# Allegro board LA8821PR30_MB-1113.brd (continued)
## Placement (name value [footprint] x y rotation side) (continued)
PR961  -  [R_0402NEW]  128.65 28.66 180 top
PR962  -  [R_0402NEW]  127.73 31.72 90 top
PR963  -  [R_0402NEW]  128.62 32.64 270 top
PR964  -  [R_0402NEW]  188.28 68.25 180 top
PR965  -  [R_0402NEW]  191.18 70.7 180 top
PR966  -  [R_0402NEW]  191.18 69.81 180 top
PR967  -  [R_0402NEW]  193.4 68.53 270 top
PR968  -  [R_0402NEW]  187.37 67.34 0 top
PR969  -  [R_0402NEW]  183.06 70.47 0 top
PR970  -  [R_0402NEW]  186.25 77.85 0 top
PR971  -  [R_0402NEW]  186 69.34 90 top
PT1  -  [TPC12]  140.67 37.63 0 top
PT2  -  [TPC12]  140.37 34.12 0 top
PT3  -  [TPC12]  193.22 59.54 0 top
PT4  -  [TPC12]  200.77 63.92 0 top
PT5  -  [TPC12]  186.7 58.46 0 top
PT6  -  [TPC12]  196.31 54.1 0 top
PT7  -  [TPC12]  110.83 49.4 180 top
PT8  -  [TPC12]  117.18 49.87 270 top
PT9  -  [TPC12]  48.33 23.9 270 top
PT10  -  [TPC12]  32.8 18.96 180 top
PT11  -  [TPC12]  17.2 65.75 180 top
PT12  -  [TPC12]  17.22 69.34 90 top
PT13  -  [TPC12]  24.7 69.25 180 top
PT14  -  [TPC12]  20.89 72.86 270 top
PT15  -  [TPC12]  29.42 63.06 0 top
PT16  -  [TPC12]  33.92 63.89 180 top
PT17  -  [TPC12]  25.31 65.52 90 top
PT18  -  [TPC12]  27.26 63.59 0 top
PT19  -  [TPC12]  189.77 79.41 0 top
PT20  -  [TPC12]  153.17 41 0 top
PU2  -  [ISL9519HRTZ-T_TQFN28_4X4]  147.12 39.46 0 bottom
PU300  -  [RT8207MZQW_WQFN20_3X3]  32.17 23.47 180 top
PU400  -  [SY8033BDBC_DFN10_3X3]  103.33 49.27 90 bottom
PU401  -  [SY8033BDBC_DFN10_3X3]  168.51 38.71 90 bottom
PU500  -  [TPS51212DSCR_SON10_3X3]  126.15 47.92 180 top
PU501  -  [RT8243BZQW_WQFN20_3X3]  194.34 57.52 180 top
PU600  -  [TPS51461RGER_QFN24_4X4]  111.36 81.21 180 bottom
PU700  -  [ISL95835HRTZ-T_TQFN40_5X5]  21.77 83.05 0 bottom
PU702  -  [INA199A2DCKR_SC70-6]  125.34 29.04 0 top
Q4  -  [SSM3K7002FU_SC70-3]  107.18 38.7 270 top
Q5  -  [SSM3K7002FU_SC70-3]  132.71 51.52 90 top
Q32  -  [SSM3K7002FU_SC70-3]  130.04 54.06 270 top
Q34  -  [SSM3K7002FU_SC70-3]  169.22 46.76 180 top
Q35  -  [DMN66D0LDW-7_SOT363-6]  150.96 67.73 180 top
Q37  -  [SSM3K7002FU_SC70-3]  59.96 46.71 90 bottom
Q38  -  [SSM3K7002FU_SC70-3]  59.96 49.13 90 bottom
Q41  -  [AO3419L_SOT23-3]  130.36 58.79 180 top
Q42  -  [SSM3K7002FU_SC70-3]  179.25 74.32 180 top
Q47  -  [SI2301CDS-T1-GE3_SOT23-3]  182.43 74.66 180 top
Q70  -  [SI3457BDV-T1-E3_TSOP6]  164.08 80.88 90 top
Q71  -  [SSM3K7002FU_SC70-3]  161.54 85.05 90 top
Q305  -  [DMN66D0LDW-7_SOT363-6]  166.11 84.69 270 top
Q311  -  [SSM3K7002FU_SC70-3]  175.32 28.35 0 top
Q316  -  [DMN66D0LDW-7_SOT363-6]  221.82 24.27 270 top
Q317  -  [DMN66D0LDW-7_SOT363-6]  227.96 8.96 90 top
Q318  -  [DMN66D0LDW-7_SOT363-6]  226.06 7.85 270 top
Q319  -  [DMN66D0LDW-7_SOT363-6]  226.06 12.68 270 top
Q320  -  [DMN66D0LDW-7_SOT363-6]  226.06 5.44 270 top
Q321  -  [SSM3K7002FU_SC70-3]  143.25 69.94 90 top
Q326  -  [SSM3K7002FU_SC70-3]  166.17 36.47 180 top
Q327  -  [DMN66D0LDW-7_SOT363-6]  176.33 39.29 0 top
Q328  -  [SSM3K7002FU_SC70-3]  177.6 31.9 0 top
Q329  -  [AO3419L_SOT23-3]  172.4 31.31 0 top
Q330  -  [SSM3K7002FU_SC70-3]  178.37 51.71 180 top
Q333  -  [SSM3K7002FU_SC70-3]  170.04 48.73 90 top
Q334  -  [SSM3K7002FU_SC70-3]  146.68 71.46 90 top
Q335  -  [SI2301CDS-T1-GE3_SOT23-3]  172.23 80.66 180 top
Q336  -  [SSM3K7002FU_SC70-3]  169.16 77.14 90 top
QC1  -  [SSM3K7002FU_SC70-3]  141.66 49.05 0 top
QC2  -  [BSS138-G_SOT23-3]  51.11 52.44 0 bottom
QC3  -  [AO4728L_SO8]  70.36 51.12 0 bottom
QC4  -  [DMN66D0LDW-7_SOT363-6]  77.78 47.44 90 bottom
QC5  -  [SSM3K7002FU_SC70-3]  90.42 65.37 270 top
QC6  -  [AP2302GN-HF_SOT23-3]  54.52 52.03 90 bottom
QD1  -  [BSS138_NL_SOT23-3]  93.53 47.74 0 bottom
QD2  -  [BSS138_NL_SOT23-3]  93.53 47.74 180 top
QH1  -  [BSS138_NL_SOT23-3]  133.85 69.79 0 top
QH3  -  [DMN66D0LDW-7_SOT363-6]  135.04 23.65 0 top
QH4  -  [DMN66D0LDW-7_SOT363-6]  126.59 57.48 90 top
QH7  -  [AO3419L_SOT23-3]  130.49 63.49 180 top
QH8  -  [AO3419L_SOT23-3]  149.66 71.69 0 top
QV1  -  [BSS138-G_SOT23-3]  211.79 76.03 90 top
R216  -  [R0603_0OHM-NEW]  137.23 48.67 90 top
R218  -  [R_0402NEW]  136.39 58.64 0 top
R219  -  [R_0402NEW]  146.39 49.36 0 top
R221  -  [R_0402NEW]  138.44 54.07 270 top
R222  -  [R_0402NEW]  216.87 24.11 270 bottom
R223  -  [R_0402NEW]  148.61 59.4 180 top
R224  -  [R_0402NEW]  148.61 60.29 180 top
R225  -  [R_0402NEW]  147.31 50.25 180 top
R226  -  [R_0402NEW]  137.28 60.45 180 top
R228  -  [R0402_0OHM-NEW]  148.61 54.7 180 top
R229  -  [R_0402NEW]  147.66 55.7 0 top
R230  -  [R_0402NEW]  147.66 57.49 0 top
R240  -  [R_0402NEW]  139.11 68.03 0 top
R241  -  [R_0402NEW]  147.66 53.81 0 top
R244  -  [R_0402NEW]  147.66 56.59 0 top
R247  -  [R_0402NEW]  147.66 58.51 0 top
R249  -  [R0402_0OHM-NEW]  136.37 59.59 0 top
R250  -  [R0402_0OHM-NEW]  136.36 56.77 0 top
R253  -  [R0402_0OHM-NEW]  140.39 67.08 270 top
R262  -  [R_0402NEW]  217.89 24.11 270 bottom
R265  -  [R0402_0OHM-NEW]  47.1 83.68 180 top
R287  -  [R_0402NEW]  128.84 52.27 90 top
R289  -  [R_0402NEW]  152.08 67.11 270 top
R290  -  [R_0402NEW]  133.15 53.4 270 top
R292  -  [R_0402NEW]  57.76 46.71 0 bottom
R293  -  [R_0402NEW]  57.76 49.13 0 bottom
R295  -  [R_0402NEW]  148.52 66.42 90 top
R296  -  [R_0402NEW]  171.35 47.08 180 top
R297  -  [R_0402NEW]  105.88 39.71 0 top
R298  -  [R_0402NEW]  134.01 50.51 180 top
R517  -  [R_0402NEW]  116.88 54.67 270 top
R531  -  [R_0603NEW]  158.6 81.88 0 top
R535  -  [R_0402NEW]  164.9 85.27 270 top
R536  -  [R_0402NEW]  162.87 84.32 90 top
R537  -  [R_0402NEW]  181.29 78.52 270 top
R538  -  [R0402_0OHM-NEW]  158.32 84.59 90 top
R540  -  [R_0402NEW]  164.14 76.03 0 top
R541  -  [R_0805NEW]  166.55 80.02 90 top
R542  -  [R_0402NEW]  166.08 85.81 0 top
R543  -  [R_0402NEW]  177.73 75.6 270 top
R545  -  [R_0402NEW]  159.06 77.81 180 top
R555  -  [R_0402NEW]  223.68 22.79 270 bottom
R556  -  [R_0402NEW]  222.71 22.79 270 bottom
R560  -  [R_0402NEW]  219.92 24.11 270 bottom
R565  -  [R_0402NEW]  218.9 24.11 270 bottom
R603  -  [R_0402NEW]  143.92 65.16 270 top
R604  -  [R_0402NEW]  136.36 54.95 0 top
R607  -  [R_0402NEW]  140.39 65.21 270 top
R608  -  [R_0402NEW]  49.37 85.81 0 top
R724  -  [R_0402NEW]  174.99 42.4 0 top
R725  -  [R_0402NEW]  178.6 38.08 180 top
R728  -  [R0402_0OHM-NEW]  178.65 45.68 0 top
R729  -  [R_0402NEW]  180.22 52.81 0 top
R730  -  [R_0402NEW]  179.6 44.79 180 top
R731  -  [R_0402NEW]  180.22 51.92 0 top
R741  -  [R0402_0OHM-NEW]  174.97 39.08 0 bottom
R742  -  [R0402_0OHM-NEW]  174.97 38.06 0 bottom
R806  -  [R_0402NEW]  205.2 54.36 270 top
R807  -  [R_0402NEW]  206.09 54.36 270 top
R808  -  [R_0402NEW]  216.05 53.56 180 top
R809  -  [R_0402NEW]  215.1 54.44 0 top
R811  -  [R_0603NEW]  138.76 48.67 90 top
R812  -  [R_0402NEW]  118.96 54.67 270 top
R817  -  [R_0402NEW]  158.99 59.84 0 top
R819  -  [R0402_0OHM-NEW]  154.9 64.35 0 top
R854  -  [R_0402NEW]  155.78 55.76 90 top
R855  -  [R_0402NEW]  154.82 55.71 90 top
R884  -  [R_0402NEW]  3.66 22.08 0 top
R886  -  [R_0402NEW]  6.44 20.41 0 top
R887  -  [R_0402NEW]  208.08 58.41 90 top
R888  -  [R_0402NEW]  212.03 59.52 0 bottom
R889  -  [R_0402NEW]  212.03 60.54 0 bottom
R890  -  [R_0402NEW]  205.32 56.22 0 bottom
R891  -  [R_0402NEW]  205.32 55.21 0 bottom
R892  -  [R_0402NEW]  205.32 53.3 0 bottom
R893  -  [R_0402NEW]  205.32 54.32 0 bottom
R894  -  [R_0402NEW]  128.84 54.97 270 top
R906  -  [R_0402NEW]  220.82 23.49 90 top
R907  -  [R_0402NEW]  229.31 7.04 270 top
R908  -  [R_0402NEW]  229.29 10.79 90 top
R909  -  [R_0402NEW]  225.1 8.88 90 top
R910  -  [R_0402NEW]  230.18 15.3 270 top
R911  -  [R_0402NEW]  230.18 11.74 270 top
R912  -  [R_0402NEW]  230.18 9.45 270 top
R913  -  [R_0402NEW]  230.18 6.09 90 top
R914  -  [R_0402NEW]  225.1 6.47 90 top
R915  -  [R_0402NEW]  229.29 9.45 270 top
R916  -  [R_0402NEW]  230.18 4.88 270 top
R917  -  [R_0402NEW]  225.1 12.25 270 top
R918  -  [R_0402NEW]  229.32 13.64 270 top
R919  -  [R_0402NEW]  225.11 5.01 270 top
R920  -  [R_0402NEW]  229.31 4.88 270 top
R921  -  [R0402_0OHM-NEW]  140.27 54.03 270 top
R922  -  [R_0402NEW]  147.66 62.06 0 top
R923  -  [R_0402NEW]  150.54 64.75 180 top
R924  -  [R_0402NEW]  136.36 53.17 0 top
R925  -  [R0402_0OHM-NEW]  148.61 62.95 180 top
R926  -  [R0402_0OHM-NEW]  123.27 26.44 180 top
R927  -  [R_0402NEW]  150.65 59.25 180 top
R928  -  [R_0402NEW]  62.03 24.38 90 top
R929  -  [R_0402NEW]  156.97 57.37 0 top
R930  -  [R_0402NEW]  142.17 67.75 270 top
R931  -  [R0402_0OHM-NEW]  145.73 66.8 90 top
R933  -  [R0402_0OHM-NEW]  143.06 66.8 90 top
R934  -  [R0402_0OHM-NEW]  143.95 66.8 90 top
R935  -  [R_0402NEW]  137.28 57.66 180 top
R936  -  [R_0402NEW]  152.46 61.14 270 top
R937  -  [R_0402NEW]  150.54 63.88 180 top
R938  -  [R_0402NEW]  142.52 71.72 180 top
R939  -  [R_0402NEW]  138.71 71.72 180 top
R940  -  [R_0402NEW]  135.06 57.78 90 top
R941  -  [R_0402NEW]  140.61 71.72 180 top
R942  -  [R_0402NEW]  179.64 25.46 270 top
R943  -  [R_0402NEW]  171.86 29.55 180 top
R944  -  [R_0402NEW]  174.32 26.33 180 top
R945  -  [R_0402NEW]  173.47 27.24 0 top
R952  -  [R_0402NEW]  10.73 26.98 270 bottom
R953  -  [R_0402NEW]  24.98 19.04 90 top
R954  -  [R_0402NEW]  142.17 64.26 90 top
R955  -  [R_0402NEW]  24.98 21.81 0 top
R957  -  [R_0402NEW]  20.29 24.88 180 top
R975  -  [R_0402NEW]  167.82 54.22 90 top
R976  -  [R_0402NEW]  157.9 55.59 180 top
R977  -  [R_0402NEW]  178.04 77.89 270 top
R978  -  [R_0402NEW]  175.13 79.77 90 top
R980  -  [R_0402NEW]  137.31 63.11 180 top
R981  -  [R_0402NEW]  147.66 63.84 0 top
R982  -  [R0402_0OHM-NEW]  144.84 66.8 90 top
R983  -  [R0402_0OHM-NEW]  129.85 78.03 270 top
R984  -  [R0402_0OHM-NEW]  134.78 80.29 270 top
R985  -  [R_0402NEW]  129.85 78.99 90 top
R986  -  [R_0402NEW]  135.68 80.29 270 top
R987  -  [R_0402NEW]  147 66.8 90 top
R989  -  [R_0402NEW]  167.28 34.51 180 bottom
R990  -  [R_0402NEW]  166.43 35.43 90 bottom
R1003  -  [R_0402NEW]  153 65.74 0 top
R1004  -  [R_0402NEW]  177.64 75.78 0 bottom
R1005  -  [R_0402NEW]  177.65 76.69 0 bottom
R1006  -  [R0402_0OHM-NEW]  165.43 75.65 90 bottom
R1007  -  [R0402_0OHM-NEW]  164.41 75.65 90 bottom
R1008  -  [R0402_0OHM-NEW]  163.51 75.63 90 bottom
R1009  -  [R0402_0OHM-NEW]  162.49 75.63 90 bottom
R1010  -  [R0402_0OHM-NEW]  160.84 75.73 90 bottom
R1011  -  [R0402_0OHM-NEW]  159.82 75.73 90 bottom
R1012  -  [R0402_0OHM-NEW]  179.73 27.27 180 top
R1013  -  [R0402_0OHM-NEW]  179.73 28.28 180 top
R1014  -  [R0402_0OHM-NEW]  179.73 29.3 180 top
R1015  -  [R0402_0OHM-NEW]  179.73 30.31 180 top
R1016  -  [R0402_0OHM-NEW]  179.73 31.33 180 top
R1017  -  [R0402_0OHM-NEW]  126.04 78.54 270 bottom
R1018  -  [R_0402NEW]  177.84 42.4 180 top
R1019  -  [R_0402NEW]  175.75 38.08 0 top
R1020  -  [R_0402NEW]  177.9 30.34 180 top
R1021  -  [R_0402NEW]  138.25 64.57 90 top
R1024  -  [R_0402NEW]  167.57 45.52 270 top
R1026  -  [R_0402NEW]  170.49 65.02 90 top
R1027  -  [R_0402NEW]  177.96 48.65 0 top
R1030  -  [R_0402NEW]  169.73 53.8 270 top
R1031  -  [R0402_0OHM-NEW]  165.83 47.97 0 top
R1032  -  [R_0402NEW]  161.19 32.35 180 top
R1033  -  [R_0402NEW]  159.06 74.27 270 bottom
R1034  -  [R_0402NEW]  161.73 73.32 90 bottom
R1035  -  [R_0402NEW]  51.75 51.43 90 top
R1036  -  [R_0402NEW]  117.66 30.6 90 top
R1037  -  [R_0402NEW]  17.8 29.43 180 top
R1038  -  [R_0402NEW]  118.55 30.6 90 top
R1039  -  [R_0402NEW]  17.8 30.82 180 top
R1040  -  [R_0402NEW]  119.44 30.6 90 top
R1041  -  [R_0402NEW]  17.8 31.71 180 top
R1042  -  [R_0402NEW]  120.33 30.6 90 top
R1043  -  [R_0402NEW]  17.8 32.6 180 top
R1044  -  [R_0402NEW]  117.66 28.06 90 top
R1045  -  [R_0402NEW]  17.8 26.89 180 bottom
R1046  -  [R_0402NEW]  118.55 28.06 90 top
R1047  -  [R_0402NEW]  17.8 26.5 180 top
R1048  -  [R_0402NEW]  118.42 26.22 270 top
R1049  -  [R_0402NEW]  17.8 27.39 180 top
R1050  -  [R_0402NEW]  119.31 26.22 270 top
R1051  -  [R_0402NEW]  17.8 28.28 180 top
R1052  -  [R_0402NEW]  114.1 28.57 90 top
R1053  -  [R_0402NEW]  17.8 29.55 180 bottom
R1054  -  [R_0402NEW]  114.99 28.57 90 top
R1055  -  [R_0402NEW]  17.8 27.77 180 bottom
R1056  -  [R_0402NEW]  115.88 28.57 90 top
R1057  -  [R_0402NEW]  17.8 28.66 180 bottom
R1058  -  [R_0402NEW]  116.77 28.57 90 top
R1059  -  [R_0402NEW]  17.8 26 180 bottom
R1060  -  [R_0402NEW]  115.15 26.84 0 top
R1061  -  [R_0402NEW]  17.8 33.11 180 bottom
R1062  -  [R_0402NEW]  115.15 25.95 0 top
R1063  -  [R_0402NEW]  17.8 32.22 180 bottom
R1064  -  [R_0402NEW]  115.15 25.06 0 top
R1065  -  [R_0402NEW]  17.8 31.33 180 bottom
R1066  -  [R_0402NEW]  115.15 24.17 0 top
R1067  -  [R_0402NEW]  17.8 30.44 180 bottom
R1068  -  [R_0402NEW]  117.66 34.47 270 top
R1069  -  [R_0402NEW]  17.8 37.17 180 top
R1070  -  [R_0402NEW]  116.77 34.47 270 top
R1071  -  [R_0402NEW]  17.8 38.06 180 top
R1072  -  [R_0402NEW]  115.88 34.47 270 top
R1073  -  [R_0402NEW]  17.8 38.95 180 top
R1074  -  [R_0402NEW]  114.99 34.47 270 top
R1075  -  [R_0402NEW]  18.07 40.74 180 top
R1076  -  [R_0402NEW]  114.1 31.36 90 top
R1077  -  [R_0402NEW]  17.8 33.62 180 top
R1078  -  [R_0402NEW]  114.99 31.36 90 top
R1079  -  [R_0402NEW]  17.8 34.51 180 top
R1080  -  [R_0402NEW]  115.87 31.36 90 top
R1081  -  [R_0402NEW]  17.8 35.39 180 top
R1082  -  [R_0402NEW]  116.75 31.36 90 top
R1083  -  [R_0402NEW]  17.8 36.28 180 top
R1084  -  [R_0603NEW]  171.51 75.82 180 top
R1086  -  [R_0402NEW]  171.27 76.86 180 top
R1089  -  [R_0402NEW]  153.91 66.62 180 top
R1090  -  [R0402_0OHM-NEW]  154.87 66.22 270 top
R1091  -  [R0402_0OHM-NEW]  139.66 72.86 0 top
R1092  -  [R_0402NEW]  155.89 62.92 270 top
R1094  -  [R_0402NEW]  147.12 72.51 90 top
R1095  -  [R_0402NEW]  154.34 73.15 90 top
R1096  -  [R_0402NEW]  153.4 73.15 90 top
R1097  -  [R_0402NEW]  152.46 73.15 90 top
R1098  -  [R_0402NEW]  153.47 71.81 270 top
R1099  -  [R_0402NEW]  155.25 73.15 90 top
R1100  -  [R_0402NEW]  115.22 50.53 0 top
R1101  -  [R_0402NEW]  151.85 69.15 0 top
R1102  -  [R_0402NEW]  151.85 70.04 0 top
R1103  -  [R_0402NEW]  137.28 55.88 180 top
R1104  -  [R_0402NEW]  162.62 59.4 90 top
R1105  -  [R_0402NEW]  156.13 74.07 270 top
R1106  -  [R_0402NEW]  148.11 70.47 180 top
R1107  -  [R0402_0OHM-NEW]  138.17 78.94 90 top
R1108  -  [R_0402NEW]  165.31 66.45 180 top
RC2  -  [R_0402NEW]  85.4 75.18 90 bottom
RC4  -  [R_0402NEW]  139.5 47.5 180 top
RC8  -  [R_0402NEW]  60.13 55.17 270 top
RC11  -  [R0402_0OHM-NEW]  138.55 46.61 0 top
RC19  -  [R_0402NEW]  145.09 47.68 270 top
RC32  -  [R_0402NEW]  59.87 80.89 90 top
RC33  -  [R_0402NEW]  58.99 81.84 270 top
RC34  -  [R_0402NEW]  58.1 80.89 90 top
RC36  -  [R_0402NEW]  85.66 65.59 270 bottom
RC41  -  [R_0402NEW]  44.08 84.78 270 bottom
RC42  -  [R_0402NEW]  113.37 52.2 270 bottom
RC43  -  [R_0402NEW]  44.97 83.83 90 bottom
RC44  -  [R_0402NEW]  45.86 84.78 270 bottom
RC45  -  [R_0402NEW]  50.7 78.19 180 top
RC46  -  [R_0402NEW]  49.17 76.42 180 bottom
RC47  -  [R_0402NEW]  50.7 77.3 180 top
RC48  -  [R_0402NEW]  49.17 77.3 180 bottom
RC49  -  [R0402_0OHM-NEW]  43.19 84.78 270 bottom
RC52  -  [R_0402NEW]  49.17 78.19 180 bottom
RC53  -  [R0402_0OHM-NEW]  46.75 84.78 270 bottom
RC54  -  [R_0402NEW]  49.17 79.08 180 bottom
RC55  -  [R_0402NEW]  60.51 53.9 270 bottom
RC56  -  [R0402_0OHM-NEW]  49.17 75.53 180 bottom
RC57  -  [R_0402NEW]  59.24 54.22 90 top
RC58  -  [R_0402NEW]  63.05 53.9 270 bottom
RC60  -  [R_0402NEW]  61.78 53.9 270 bottom
RC72  -  [R_0402NEW]  52 49.52 90 top
RC74  -  [R_0402NEW]  48.7 51.43 90 top
RC75  -  [R_0402NEW]  49.97 49.52 90 top
RC76  -  [R_0402NEW]  30.36 50.24 0 top
RC77  -  [R_0402NEW]  49.84 52.38 270 top
RC78  -  [R_0402NEW]  53.65 80.89 90 top
RC81  -  [R_0402NEW]  42.29 83.87 90 bottom
RC86  -  [R_0402NEW]  49.17 82.13 180 bottom
RC87  -  [R_0402NEW]  52.76 80.89 90 top
RC89  -  [R_0402NEW]  58.04 77.08 270 top
RC92  -  [R0402_0OHM-NEW]  62.56 80.91 90 top
RC93  -  [R_0402NEW]  61.67 80.91 90 top
RC94  -  [R_0402NEW]  60.78 80.91 90 top
RC95  -  [R_0402NEW]  60.84 78.8 90 top
RC96  -  [R0402_0OHM-NEW]  59.95 78.8 90 top
RC97  -  [R_0402NEW]  50.44 82.77 180 top
RC98  -  [R0402_0OHM-NEW]  50.44 81.88 180 top
RC99  -  [R0402_0OHM-NEW]  50.44 80.99 180 top
RC100  -  [R_0402NEW]  50.44 80.1 180 top
RC101  -  [R_0402NEW]  75.93 51.41 0 bottom
RC102  -  [R_0402NEW]  79.69 44.83 90 bottom
RC103  -  [R_0402NEW]  65.41 47.03 180 bottom
RC104  -  [R_0402NEW]  75.8 47.22 0 bottom
RC105  -  [R_0402NEW]  77.78 51.41 0 bottom
RC106  -  [R_0402NEW]  56.81 49.13 180 bottom
RC107  -  [R0402_0OHM-NEW]  75.8 48.11 0 bottom
RC109  -  [R0805_0OHM-NEW]  89.47 52.97 90 bottom
RC112  -  [R_0402NEW]  56.81 46.71 180 bottom
RC116  -  [R_0402NEW]  57.11 58 0 top
RC126  -  [R_0402NEW]  74.99 62.1 90 top
RC129  -  [R_0402NEW]  74.1 62.1 90 top
RC130  -  [R_0402NEW]  126.04 79.5 90 bottom
RC135  -  [R_0402NEW]  56.32 81.83 270 top
RC136  -  [R_0402NEW]  55.43 80.91 90 top
RC137  -  [R_0402NEW]  77.67 67.7 90 top
RC138  -  [R_0402NEW]  92.89 63.68 270 top
RC141  -  [R_0402NEW]  57.13 57.11 0 top
RC142  -  [R_0402NEW]  54.54 81.84 270 top
RC143  -  [R_0402NEW]  58.99 76.19 90 top
RC144  -  [R_0402NEW]  58.99 75.24 270 top
RC145  -  [R0402_0OHM-NEW]  50.98 49.52 90 top
RCU1  -  [R_0402NEW]  53.83 49.62 0 bottom
RD1  -  [R_0402NEW]  101.94 20.03 0 bottom
RD2  -  [R_0402NEW]  113.76 25.03 270 top
RD3  -  [R_0402NEW]  91.66 20.28 0 bottom
RD4  -  [R_0402NEW]  100.99 20.03 180 top
RD5  -  [R_0402NEW]  81.24 20.28 0 bottom
RD6  -  [R_0402NEW]  90.7 20.28 180 top
RD7  -  [R_0402NEW]  68.51 37.03 90 bottom
RD8  -  [R_0402NEW]  79.65 20.28 180 top
RD9  -  [R_0402NEW]  53.11 42.13 180 bottom
RD10  -  [R_0402NEW]  65.51 31.73 0 top
RD11  -  [R_0402NEW]  42.81 42.15 0 bottom
RD12  -  [R_0402NEW]  49.89 41.72 0 top
RD13  -  [R_0402NEW]  30.06 25.87 0 bottom
RD14  -  [R_0402NEW]  41.66 25.77 0 top
RD15  -  [R_0402NEW]  26.13 41.45 90 bottom
RD16  -  [R_0402NEW]  29.28 25.82 180 top
RD17  -  [R_0402NEW]  110.18 20.17 270 top
RD18  -  [R_0402NEW]  18.07 43.41 180 top
RD19  -  [R_0402NEW]  111.07 20.17 270 top
RD20  -  [R_0402NEW]  16.15 42.51 180 top
RD21  -  [R_0402NEW]  117.15 37.39 270 top
RD22  -  [R_0402NEW]  17.86 42 180 bottom
RD25  -  [R_0402NEW]  116.26 36.44 90 top
RD26  -  [R_0402NEW]  16.91 41.11 0 bottom
RD27  -  [R_0402NEW]  90.88 48.33 270 bottom
RD29  -  [R_0402NEW]  90.88 46.43 270 bottom
RD30  -  [R_0402NEW]  91.07 47.9 270 top
RD32  -  [R_0402NEW]  91.07 46 270 top
RD33  -  [R_0402NEW]  114.1 34.47 270 top
RD34  -  [R_0402NEW]  17.8 39.84 180 top
RD35  -  [R_0402NEW]  118.84 33.62 0 top
RD36  -  [R_0402NEW]  17.8 34.89 180 bottom
RD37  -  [R_0402NEW]  118.84 32.73 0 top
RD38  -  [R_0402NEW]  17.8 34 180 bottom
RD39  -  [R_0402NEW]  59.27 53.3 0 top
RD40  -  [R_0402NEW]  59.27 52.41 0 top
RD41  -  [R_0402NEW]  70.07 54.06 0 top
RD42  -  [R_0402NEW]  70.07 53.17 0 top
RH2  -  [R_0402NEW]  119.01 63.09 90 top
RH11  -  [R_0402NEW]  116.99 64.35 180 top
RH23  -  [R_0402NEW]  120 66.45 270 bottom
RH24  -  [R_0402NEW]  118.9 71.34 180 top
RH25  -  [R_0402NEW]  123.17 58.36 180 top
RH27  -  [R_0402NEW]  116.48 68.41 180 top
RH28  -  [R_0402NEW]  118.77 69.3 180 top
RH29  -  [R_0402NEW]  107.02 52.41 0 top
RH30  -  [R_0402NEW]  118.9 70.45 180 top
RH31  -  [R_0402NEW]  123.04 64.13 90 top
RH32  -  [R_0402NEW]  112.5 51.43 90 bottom
RH33  -  [R_0402NEW]  130.41 70.89 0 top
RH34  -  [R_0402NEW]  123.91 64.13 90 top
RH35  -  [R_0402NEW]  107.47 51.43 90 bottom
RH36  -  [R_0402NEW]  130.41 69.94 0 top
RH37  -  [R_0402NEW]  112.58 48.89 90 bottom
RH38  -  [R_0402NEW]  116.01 53.72 90 top
RH39  -  [R_0402NEW]  118.95 55.92 180 top
RH40  -  [R_0402NEW]  106.69 53.72 90 top
RH41  -  [R_0402NEW]  108.52 59.81 90 top
RH42  -  [R_0402NEW]  115.03 70.45 0 top
RH43  -  [R_0402NEW]  104.02 54.67 270 top
RH44  -  [R_0402NEW]  114.74 57.59 270 top
RH45  -  [R_0402NEW]  120.23 55.88 0 top
RH46  -  [R_0402NEW]  105.8 54.67 270 top
RH48  -  [R_0402NEW]  104.91 54.67 270 top
RH53  -  [R_0402NEW]  112.49 63.08 0 top
RH54  -  [R_0402NEW]  125.07 83.34 180 bottom
RH56  -  [R_0402NEW]  135.41 78.96 180 bottom
RH57  -  [R_0402NEW]  125.07 82.45 180 bottom
RH67  -  [R_0402NEW]  117.95 58.66 0 top
RH69  -  [R_0402NEW]  118.09 54.67 270 top
RH70  -  [R_0402NEW]  115 54.67 270 top
RH72  -  [R_0402NEW]  120.07 56.04 270 bottom
RH73  -  [R_0402NEW]  124.69 56.48 0 top
RH74  -  [R_0402NEW]  127.95 58.98 270 top
RH75  -  [R_0402NEW]  116.12 63.44 0 top
RH76  -  [R_0402NEW]  95.15 64.99 180 top
RH77  -  [R_0402NEW]  95.16 62.08 180 top
RH78  -  [R_0402NEW]  100.61 66.89 180 top
RH79  -  [R_0402NEW]  95.15 63.08 180 top
RH80  -  [R_0402NEW]  113.34 65.02 90 top
RH81  -  [R_0402NEW]  114.48 65.97 270 top
RH82  -  [R_0402NEW]  104.53 58.86 90 top
RH83  -  [R_0402NEW]  104.53 57.9 270 top
RH84  -  [R_0402NEW]  120.58 78.35 90 top
RH86  -  [R_0402NEW]  121.47 79.3 270 top
RH89  -  [R_0402NEW]  122.72 77.87 90 bottom
RH91  -  [R_0402NEW]  111.94 51.43 90 top
RH95  -  [R_0402NEW]  109.45 54.67 270 top
RH98  -  [R_0402NEW]  133.29 22.57 0 top
RH99  -  [R_0402NEW]  137.45 25.29 90 top
RH100  -  [R_0402NEW]  110.38 54.67 270 top
RH103  -  [R_0402NEW]  120.07 53.08 90 bottom
RH105  -  [R_0402NEW]  134.04 24.98 270 top
RH107  -  [R_0402NEW]  121.18 56.77 180 top
RH110  -  [R_0402NEW]  114.06 53.72 90 top
RH111  -  [R_0402NEW]  137.45 23.46 90 top
RH112  -  [R_0402NEW]  117.77 51.66 90 bottom
RH113  -  [R_0402NEW]  107.37 73.84 270 top
RH116  -  [R_0402NEW]  113.47 48.89 90 bottom
RH117  -  [R_0402NEW]  113.67 79.66 270 top
RH118  -  [R_0402NEW]  115.17 51.44 90 bottom
RH123  -  [R_0402NEW]  111.34 74.13 0 top
RH124  -  [R_0402NEW]  94.2 64.1 0 top
RH125  -  [R_0402NEW]  92.87 62.81 90 bottom
RH126  -  [R_0402NEW]  126.58 64.13 90 top
RH128  -  [R_0402NEW]  118.98 52.38 270 top
RH130  -  [R0402_0OHM-NEW]  118.86 60.41 180 top
RH131  -  [R0402_0OHM-NEW]  122.26 59.41 0 top
RH132  -  [R0402_0OHM-NEW]  116.9 52.82 270 bottom
RH133  -  [R0402_0OHM-NEW]  125.69 65.08 270 top
RH137  -  [R0402_0OHM-NEW]  117.95 59.52 0 top
RH140  -  [R_0402NEW]  112.36 76.67 0 top
RH141  -  [R_0402NEW]  111.32 54.67 270 top
RH143  -  [R_0402NEW]  116.14 52.39 270 top
RH145  -  [R_0402NEW]  117.95 57.72 0 top
RH146  -  [R_0402NEW]  118.09 51.47 90 top
RH147  -  [R_0402NEW]  118.8 67.14 180 top
RH150  -  [R_0402NEW]  120.23 58.64 0 top
RH151  -  [R_0402NEW]  118.8 68.03 180 top
RH154  -  [R_0402NEW]  150.65 61.05 180 top
RH158  -  [R_0402NEW]  167.54 67.02 180 top
RH159  -  [R_0402NEW]  124.78 64.13 90 top
RH163  -  [R_0402NEW]  116.48 69.3 180 top
RH164  -  [R_0402NEW]  121.85 77.87 90 bottom
RH165  -  [R_0402NEW]  119.15 79.59 180 top
RH168  -  [R_0402NEW]  133.36 76.42 180 top
RH171  -  [R_0402NEW]  133.36 77.3 180 top
RH174  -  [R_0402NEW]  137.31 62.22 180 top
RH175  -  [R_0402NEW]  100.86 59.65 180 top
RH176  -  [R_0402NEW]  95.4 59.52 180 top
RH177  -  [R_0402NEW]  114.31 50.7 90 bottom
RH180  -  [R_0402NEW]  120.1 73.35 90 top
RH181  -  [R_0402NEW]  112.25 54.67 270 top
RH182  -  [R_0402NEW]  113.13 53.72 90 top
RH183  -  [R_0402NEW]  131.44 76.97 90 top
RH186  -  [R_0402NEW]  118.9 62.19 180 top
RH188  -  [R_0402NEW]  118 56.78 0 top
RH190  -  [R_0402NEW]  121.18 57.7 180 top
RH193  -  [R_0402NEW]  108.51 54.67 270 top
RH196  -  [R_0402NEW]  109.79 52.38 270 top
RH197  -  [R_0402NEW]  108.9 52.38 270 top
RH201  -  [R_0603NEW]  96.76 56.6 0 top
RH207  -  [R0603_0OHM-NEW]  91.37 55.16 270 bottom
RH208  -  [R_0603NEW]  92.59 64.99 180 bottom
RH210  -  [R0603_0OHM-NEW]  109.91 63.49 90 top
RH211  -  [R0603_0OHM-NEW]  103.18 57.7 270 top
RH213  -  [R_0603NEW]  105.98 74.21 270 top
RH214  -  [R_0603NEW]  123.25 54.78 270 top
RH216  -  [R_0805NEW]  92.13 70.37 90 top
RH219  -  [R0603_0OHM-NEW]  92.59 70.07 180 bottom
RH222  -  [R_0402NEW]  133.37 65.11 180 top
RH227  -  [R_0402NEW]  128.96 72.45 270 top
RH230  -  [R0805_0OHM-NEW]  134.42 67.58 180 top
RH233  -  [R0603_0OHM-NEW]  91.17 66.51 0 bottom
RH234  -  [R_0603NEW]  92.59 68.03 180 bottom
RH244  -  [R0603_0OHM-NEW]  111.06 67.96 90 top
RH247  -  [R0805_0OHM-NEW]  86.16 68.85 90 bottom
RH248  -  [R_0402NEW]  111.69 48.89 90 bottom
RH255  -  [R0402_0OHM-NEW]  107.88 57.02 90 top
RH256  -  [R_0402NEW]  139.2 80.48 180 bottom
RH257  -  [R_0402NEW]  107.58 54.67 270 top
RH258  -  [R_0402NEW]  101.85 52.92 0 bottom
RH259  -  [R_0402NEW]  27.48 48.56 90 bottom
RH262  -  [R_0402NEW]  179.25 41.46 270 top
RH263  -  [R_0402NEW]  110.67 52.38 270 top
RH270  -  [R_0402NEW]  115.25 52.39 270 top
RH271  -  [R_0402NEW]  117.82 74.16 0 top
RH272  -  [R_0402NEW]  112.81 52.38 270 top
RH273  -  [R0402_0OHM-NEW]  113.72 51.43 90 top
RH274  -  [R_0402NEW]  106.29 52.41 180 bottom
RH275  -  [R_0402NEW]  130.41 71.84 0 top
RH276  -  [R_0402NEW]  111.56 51.43 90 bottom
RH279  -  [R_0402NEW]  130.41 69.05 0 top
RH280  -  [R0603_0OHM-NEW]  88.58 43.95 90 bottom
RH281  -  [R_0402NEW]  169.76 62.45 0 top
RH282  -  [R_0402NEW]  172.62 62.45 180 top
RH290  -  [R_0402NEW]  119.18 52.54 270 bottom
RH291  -  [R_0402NEW]  115.72 72.48 180 top
RH292  -  [R0603_0OHM-NEW]  107.25 59.07 90 top
RH293  -  [R0402_0OHM-NEW]  117.95 61.28 0 top
RH294  -  [R_0402NEW]  175.57 46.1 90 top
RH295  -  [R_0402NEW]  133.37 66 180 top
RH296  -  [R_0402NEW]  122.39 77.94 0 top
RH297  -  [R0402_0OHM-NEW]  150.65 60.16 180 top
RH298  -  [R_0402NEW]  123.55 73.85 180 bottom
RH299  -  [R_0402NEW]  147.66 61.18 0 top
RH300  -  [R_0402NEW]  211.21 73.49 180 top
RH301  -  [R_0402NEW]  120.15 73.45 90 bottom
RH302  -  [R_0402NEW]  118.33 77.81 0 top
RH303  -  [R_0402NEW]  108.36 52.38 270 bottom
RH304  -  [R_0402NEW]  110.12 52.38 270 bottom
RH305  -  [R_0402NEW]  120.2 76.95 0 bottom
RH306  -  [R_0402NEW]  122.39 76.95 0 top
RH307  -  [R_0402NEW]  117.82 73.27 0 top
RH308  -  [R_0402NEW]  121.06 73.45 90 bottom
RH309  -  [R0402_0OHM-NEW]  127.9 65.09 270 top
RH310  -  [R0402_0OHM-NEW]  119.87 52.38 270 top
RH311  -  [R_0402NEW]  121.18 60.85 180 top
RH312  -  [R0603_0OHM-NEW]  124.77 54.78 270 top
RH313  -  [R0402_0OHM-NEW]  133.15 54.35 90 top
RH314  -  [R_0402NEW]  120.99 73.35 90 top
RH315  -  [R_0402NEW]  119.05 72.25 180 top
RH316  -  [R_0402NEW]  109.25 51.43 90 bottom
RH317  -  [R_0402NEW]  126.46 63.21 0 top
RH318  -  [R_0402NEW]  126.84 62.19 0 top
RH319  -  [R_0402NEW]  126.84 61.3 0 top
RH320  -  [R_0402NEW]  126.84 60.41 0 top
RH321  -  [R_0402NEW]  123.92 63.08 0 top
RH322  -  [R_0402NEW]  123.92 62.19 0 top
RH323  -  [R_0402NEW]  123.92 61.3 0 top
RH324  -  [R_0402NEW]  123.92 60.41 0 top
RH325  -  [R_0402NEW]  123.34 76.03 180 top
RH326  -  [R_0402NEW]  123.34 74.26 180 top
RH327  -  [R_0402NEW]  123.34 75.15 180 top
RH328  -  [R_0402NEW]  125.31 73.88 0 top
RH329  -  [R_0402NEW]  125.31 74.76 0 top
RH330  -  [R_0402NEW]  125.31 75.65 0 top
RH331  -  [R_0402NEW]  125.37 77.43 180 top
RH332  -  [R_0402NEW]  123.86 75.2 180 bottom
RH333  -  [R_0402NEW]  123.86 76.06 180 bottom
RH334  -  [R_0402NEW]  123.86 76.92 180 bottom
RH335  -  [R_0402NEW]  124.52 77.85 90 bottom
RH336  -  [R0402_0OHM-NEW]  119.84 54.66 270 top
RH337  -  [R_0402NEW]  104.52 52.43 180 bottom
RH338  -  [SHORTPADS]  96.27 42.68 180 top
RH339  -  [SHORTPADS]  125.1 74.23 180 bottom
RRF1  -  [R_0402NEW]  158.62 27.94 180 bottom
RRF2  -  [R_0402NEW]  161.67 27.06 90 bottom
RV1  -  [R_1206NEW]  204.85 73.11 180 top
RV2  -  [R_0402NEW]  168.93 58.51 180 top
RV3  -  [R_0402NEW]  173.89 55.71 180 top
RV4  -  [R_0402NEW]  213.65 72.68 180 bottom
RV8  -  [R0402_0OHM-NEW]  212.9 74.47 0 bottom
RV9  -  [R_0402NEW]  213.81 73.58 180 bottom
RV10  -  [R_0402NEW]  212.49 75.58 180 bottom
SW1  -  [SW_EVQP3S01K_4P]  230.38 25.28 270 top
SW2  -  [SW_SKQGABE010_4P]  144.91 78.25 0 bottom
T1  -  [TPC12]  58.86 78.57 0 top
T76  -  [TPC12]  113.67 58.05 0 top
T81  -  [TPC12]  107.37 76.21 0 top
T82  -  [TPC12]  108.72 76.7 0 top
T123  -  [TPC12]  113.89 53.17 180 bottom
T127  -  [TPC12]  111.23 57.47 0 top
T166  -  [TPC12]  113.57 72.2 0 top
T204  -  [TPC12]  114.25 74.27 0 top
T208  -  [TPC12]  57.03 79.25 90 top
T209  -  [TPC12]  56.42 78.42 90 top
T210  -  [TPC12]  57.04 76.07 90 top
T211  -  [TPC12]  58.1 73.74 90 top
T212  -  [TPC12]  55.86 74.92 90 top
T213  -  [TPC12]  49.21 81.37 90 bottom
T214  -  [TPC12]  57.08 78.42 90 top
T215  -  [TPC12]  56.79 73.8 90 top
T216  -  [TPC12]  115.81 58.76 0 top
T218  -  [TPC12]  115.26 60.77 0 top
T219  -  [TPC12]  116.83 61.9 0 top
T223  -  [TPC12]  71.38 59.14 270 top
T224  -  [TPC12]  54.05 77.1 0 top
T225  -  [TPC12]  53.73 78.4 0 top
T226  -  [TPC12]  48.57 81.37 180 bottom
T227  -  [TPC12]  55.28 76.61 0 top
T228  -  [TPC12]  49.21 80.61 180 bottom
T229  -  [TPC12]  48.57 80.61 180 bottom
T230  -  [TPC12]  49.21 79.9 180 bottom
T231  -  [TPC12]  48.57 79.9 180 bottom
T232  -  [TPC12]  57.74 79.41 0 top
T233  -  [TPC12]  52.36 74.94 0 top
T234  -  [TPC12]  54.12 73.85 0 top
T235  -  [TPC12]  55.18 77.89 0 top
T236  -  [TPC12]  56.22 76.19 0 top
T237  -  [TPC12]  57.22 75.03 0 top
T238  -  [TPC12]  57.26 77.59 0 top
T239  -  [TPC12]  102.28 58.85 0 top
T240  -  [TPC12]  101.66 57.56 0 top
T241  -  [TPC12]  55.46 73.66 0 top
T242  -  [TPC12]  167.22 50.48 0 top
T243  -  [TPC12]  168.51 50.84 0 top
T244  -  [TPC12]  176.84 49.26 0 top
T245  -  [TPC12]  177.1 47.71 0 top
T246  -  [TPC12]  176.56 46.47 0 top
T247  -  [TPC12]  98.99 59.91 0 top
T248  -  [TPC12]  56.38 77.15 0 top
T249  -  [TPC12]  161.65 66.97 0 top
T250  -  [TPC12]  152.41 64.27 0 top
T252  -  [TPC12]  164.07 67.68 0 top
T253  -  [TPC12]  161.16 60.35 0 top
U34  -  [KB9012BF-A3_LFBGA_128P]  145.42 62.1 270 top
U48  -  [W25Q64CVSSIG_SO8]  127.62 80.61 90 bottom
U635  -  [SN74LVC1G06DCKR_SC70-5]  52.6 85.64 180 top
U636  -  [STM32F103RDY6TR_WLCSP_64P]  158.05 62.32 90 top
U637  -  [DE303DLHCTR_LGA14_3X5]  155.49 53.33 180 top
U638  -  [TX3GD20TR_LGA16_4X4]  139.86 77.36 270 top
U652  -  [AT97SC3204-X2A14-AB_TSSOP28]  165.66 49.47 90 top
U654  -  [TPS22966DPUR_SON14_2X3]  172.16 65.73 0 top
U655  -  [TPS22966DPUR_SON14_2X3]  172 53.79 270 top
U656  -  [G547I2P81U_MSOP8]  209.71 57.71 270 top
U657  -  [G547I2P81U_MSOP8]  209.71 61.26 270 top
UC1  -  [74AHC1G09GW_TSSOP5]  141.05 47.64 270 top
UC2  -  [SN74LVC1G07DCKR_SC70-5]  127.46 77.8 90 bottom
UCPU1  -  [IVY-BRIDGE_BGA_1023P]  82.1 79.79 180 bottom
UD1  -  [MT41K256M8DA-15E-M_FBGA_78P]  110.27 33.4 180 bottom
UD2  -  [MT41K256M8DA-15E-M_FBGA_78P]  103.87 33.4 0 top
UD3  -  [MT41K256M8DA-15E-M_FBGA_78P]  99.22 33.4 180 bottom
UD4  -  [MT41K256M8DA-15E-M_FBGA_78P]  92.82 33.4 0 top
UD5  -  [MT41K256M8DA-15E-M_FBGA_78P]  88.17 33.4 180 bottom
UD6  -  [MT41K256M8DA-15E-M_FBGA_78P]  81.77 33.4 0 top
UD7  -  [MT41K256M8DA-15E-M_FBGA_78P]  77.12 33.4 180 bottom
UD8  -  [MT41K256M8DA-15E-M_FBGA_78P]  70.72 33.4 0 top
UD9  -  [MT41K256M8DA-15E-M_FBGA_78P]  61.63 38.48 180 bottom
UD10  -  [MT41K256M8DA-15E-M_FBGA_78P]  55.22 38.48 0 top
UD11  -  [MT41K256M8DA-15E-M_FBGA_78P]  50.58 38.48 180 bottom
UD12  -  [MT41K256M8DA-15E-M_FBGA_78P]  44.18 38.48 0 top
UD13  -  [MT41K256M8DA-15E-M_FBGA_78P]  39.53 38.48 180 bottom
UD14  -  [MT41K256M8DA-15E-M_FBGA_78P]  33.13 38.48 0 top
UD15  -  [MT41K256M8DA-15E-M_FBGA_78P]  28.48 38.48 180 bottom
UD16  -  [MT41K256M8DA-15E-M_FBGA_78P]  22.08 38.48 0 top
UD17  -  [AT24C02B-TH-T_TSSOP8]  62.18 53.13 270 top
UD18  -  [AT24C02B-TH-T_TSSOP8]  72.6 53.9 270 top
UH1  -  [BD82QS77-QPRF-C1_BGA_1017P]  116.75 56.13 270 bottom
UH5  -  [SN74AHC1G08DCKR_SC70-5]  136.25 75.4 0 top
UI1  -  [SLG55584AVTR_TDFN8_2X2]  213.19 52.93 90 top
URF1  -  [SKY13351-378LF_QFN6_1X1]  159.79 28.07 0 bottom
UV1  -  [SN74CBT3257CPWR_TSSOP16]  171.16 61.42 270 top
Y1  -  [Y_CM31532768DZFT_2P]  155.91 69.68 0 top
Y2  -  [Y_X1H008000DI1H-W_4P]  160.23 69.12 0 top
YH1  -  [Y_CM31532768DZFT_2P]  121.46 62.45 90 top
YH2  -  [Y_X3G025000DI1H-H_4P]  115.16 79.8 270 top

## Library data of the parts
C265 C276-C286 C352 C612 C613 C617 C654-C656 C708-C711 C713-C716 C720-C722 C961 C963-C966 C974 C976-C979 C1078 C1098-C1102 C1110 C1116-C1118 C1122-C1125 C1133 C1135-C1142 C1145 C1146 C1151 C1152 C1154-C1158 C1160 C1161 C1163 C1164 C1167-C1170 C1173-C1200 C1204-C1207 CC65 CC68 CC69 CC174 CC175 CC181-CC184 CC217-CC224 CC226-CC230 CC233-CC242 CD1 CD3 CD5 CD7 CD29 CD33 CD37 CD41 CD57 CD59 CD61 CD63 CD85 CD87 CD89 CD91 CD113-CD124 CD127-CD129 CD132 CD133 CD135 CD136 CD139 CD140 CD142 CH2-CH6 CH21-CH26 CH28 CH36 CH38-CH48 CH50-CH56 CH59-CH65 CH67-CH72 CH74-CH78 CH80-CH85 CH87 CH89 CH94 CH95 CH99 CH102 CH103 CH107 CH116-CH118 CH1202 CH1203 CRF1-CRF5 CV2 CV13 CV14 PC19-PC23 PC25 PC29-PC31 PC33 PC35-PC39 PC41 PC45 PC201 PC202 PC206 PC207 PC216 PC218-PC221 PC303 PC304 PC309 PC312-PC314 PC401 PC404 PC406 PC407 PC500 PC501 PC505 PC507-PC511 PC603 PC606 PC609 PC612 PC613 PC616-PC619 PC700-PC703 PC706-PC708 PC710-PC712 PC714 PC715 PC728-PC730 PC733 PC737-PC739 PC741-PC750 PC900-PC907 PC909-PC911 PC1225-PC1240 PC1285-PC1323 PC1910 PC1914-PC1916 PC1919 PC1920 = C_0402NEW
C293 C355 C707 C712 C719 C962 C968-C970 C1059 C1143 C1153 C1159 C1162 C1165 C1171 C1172 CC138 CC139 CC160-CC165 CC167-CC170 CC172 CC225 CC231 CC232 CD2 CD4 CD6 CD8 CD30 CD34 CD38 CD42 CD58 CD60 CD62 CD64 CD86 CD88 CD90 CD92 CH49 CH66 CH73 CH79 CV1 PC32 PC34 PC124 PC125 PC208 PC209 PC212 PC213 PC215 PC217 PC301 PC307 PC310 PC311 PC405 PC409 PC504 PC506 PC600-PC602 PC713 PC717-PC719 PC740 PC908 PC1256-PC1273 PC1911 PC1918 = C_0603NEW
C303 C1109 CC166 CC171 CD125 CD126 CH86 CH88 PC210 PC214 PC224 = C_B2
C621 C623 C1060-C1065 C1107 C1108 CH11 CH16 CS42 CS43 CS53 CS54 CV3-CV12 = C_0402NEW: signal model: C_0402_C_0402
CC176 PC1921 = C_D2
CH27 CH35 CH37 CH57 CH58 CV15 PC15-PC18 PC24 PC26-PC28 PC43 PC44 PC203-PC205 PC222 PC300 PC302 PC305 PC306 PC400 PC402 PC403 PC408 PC410 PC411 PC502 PC503 PC604 PC605 PC607 PC608 PC610 PC611 PC614 PC615 PC704 PC705 PC709 PC734-PC736 PC850-PC856 PC858-PC862 PC890-PC894 PC913-PC916 PC1908 PC1909 PC1912 PC1913 PC1917 = C_0805NEW
CLRP1 CLRP2 RH338 RH339 = SHORTPADS: User Part Number: PART#
D50 D90 = IP4223CZ6_SO6
D72 D73 D81 D92 = SDMK0340L-7-F_SOD323-2
D74 D82 = LXES4XBAA6-027_MSOP8
D83 D93 DH4 = BAT54CW-7-F_SOT323-3
D84 D85 = RB751V-40GTE-17_SOD323-2
DE1 DE2 = PESD5V0U2BT_SOT23-3
DH2 DH3 = RB751S40T1_SOD523-2
DV1 DV2 = D_RCLAMP0524PPTCT
F1 = F_1812L075-24DR
FD1-FD6 = FIDUCIAL_C40M80
FV1 = F_1206L150PR
H1 H5-H8 = H_2P3
H3 = H_4P0
H9-H12 H14 = H_3P2
H13 = H_4P5N
H16 = H_2P0X2P5N
H17 = H_2P0N
H19-H21 = EMI-79X138
JANT1-JANT3 = HRS_UPFL-R-SMT-1-10_3P
JBATT9 = FOX_GS73091-10272-7H_9P-T
JBL1 = ACES_50519-00401-P01_4P-T
JDCIN1 = ACES_50281-00501-001_5P-T
JFAN1 = ACES_50281-0040N-001_4P
JIOL1 = E-T_1001-F36E-03R_36P
JKB1 = ACES_50699-03041-001_30P-T
JLVDS1 JLVDS2 = ACES_50406-02071-001_20P
JMDP1 = ACON_MAR2B-20K1200_20P-T
JP1 PJP702 = JUMP_43X39
JRTC1 = ACES_50271-00201-001_2P
JSATA1 = TYCO_2041119-1_52P
JTP1 = TYCO_2041084-6_6P
JUSB1 = TAIWI_USB014-107CRL-TW_10P-T
JUSB2 = ACON_TARAG-9V1391_9P-T
JWLAN1 = BELLW_80019-1021_52P
L40 L52 L55 = SW_WCM2012F2S_4P: signal model: SW_WCM2012F2S_4P_SW_WCM2012F2S_4P
L43 L44 = KC_FBMA-L11-160808-800LMT_2P
L45 = MURAT_DLW21SN670HQ2L_4P: signal model: R_0402_R_0402
L46 L53 L54 L56 L57 = MURAT_DLW21SN670HQ2L_4P: signal model: MURAT_DLW21SN670HQ2L_4P_MURAT_DLW21SN670HQ2L_4P
L49 = SW_WCM2012F2S_4P
L58 = MURAT_DLW21SN670HQ2L_4P
L59 L60 = MURAT_BLM18AG601SN1D_L0603_2P
LED1-LED5 = LED_27-11-T1D-CP1Q1RY-3C_2P
LH3 = MURAT_LQM21FN1R0N00D_2P
LH4 LH6-LH8 = MURAT_LQM21FN100M80L_2P
LH9 = MURAT_BLM18BA220SN1D_2P
PC308 PC980 PC981 PC984 PC986 PC990 PC991 PC993 PC995 = C_B
PC987 PC994 PC1900 PC1901 PC1903 = C_D2E
PD5 = D_EC31QS04
PD9 = BAS40CW_SOT323-3
PD10 PD903 PD906 PD907 PD909 = RB751V-40_SOD323-2
PD11 = GLZ5P1B_LL34-2
PD200 = BZT52-B5V6S_SOD323-2
PD901 = BAV99W-7-F_SOT323-3
PD902 PD904 PD905 PQ903 = TP0610K-T1-E3_SOT23-3
PH700-PH703 PH901 PR14-PR20 PR22 PR28 PR29 PR31 PR33 PR34 PR36-PR38 PR40 PR41 PR43-PR45 PR47-PR49 PR104 PR200-PR203 PR210-PR212 PR216 PR218 PR301 PR304 PR305 PR307 PR308 PR323 PR401 PR403 PR404 PR407-PR409 PR500 PR502 PR505-PR507 PR510 PR514 PR515 PR600-PR603 PR607-PR609 PR700-PR709 PR712 PR715-PR717 PR719 PR725-PR728 PR733 PR734 PR737 PR738 PR740 PR741 PR744 PR748-PR750 PR900-PR906 PR908-PR910 PR913 PR915-PR917 PR935 PR937 PR938 PR941 PR943 PR957-PR971 R218 R219 R221 R223-R226 R229 R230 R240 R241 R244 R247 R287 R289 R290 R292 R293 R295-R298 R517 R535-R537 R540 R542 R543 R545 R603 R604 R607 R608 R724 R725 R729-R731 R806-R809 R812 R817 R854 R855 R884 R886 R887 R894 R906-R920 R922-R924 R927-R930 R935-R945 R952-R955 R957 R975-R978 R980 R981 R985-R987 R989 R990 R1003 R1018-R1021 R1024 R1026 R1027 R1030 R1032-R1083 R1086 R1089 R1092 R1094-R1106 R1108 RC2 RC4 RC8 RC19 RC32-RC34 RC36 RC41-RC48 RC52 RC54 RC55 RC57 RC58 RC60 RC72 RC74-RC78 RC81 RC86 RC87 RC89 RC93-RC95 RC97 RC100-RC106 RC112 RC116 RC126 RC129 RC130 RC135-RC138 RC141-RC144 RCU1 RD1-RD22 RD25-RD27 RD29 RD30 RD32-RD42 RH2 RH11 RH23-RH25 RH27-RH46 RH48 RH53 RH54 RH56 RH57 RH67 RH69 RH70 RH72-RH84 RH86 RH89 RH91 RH95 RH98-RH100 RH103 RH105 RH107 RH110-RH113 RH116-RH118 RH123-RH126 RH128 RH140 RH141 RH143 RH145-RH147 RH150 RH151 RH154 RH158 RH159 RH163-RH165 RH168 RH171 RH174-RH177 RH180-RH183 RH186 RH188 RH190 RH193 RH196 RH197 RH222 RH227 RH248 RH256-RH259 RH262 RH263 RH270-RH272 RH274-RH276 RH279 RH281 RH282 RH290 RH291 RH294-RH296 RH298-RH308 RH311 RH314-RH335 RH337 RRF1 RRF2 RV2-RV4 RV9 RV10 = R_0402NEW
PJP200 PJP205 PJP303 PJP501 PJP502 PJP601 PJP700 PJP701 = JUMP_43X118
PJP201-PJP204 PJP301 PJP400-PJP403 PJP500 PJP507 PJP508 PJP600 = JUMP_43X79
PL201 = TOKO_FDSD0630-H-2R2M-P3_2P
PL400 PL401 = TAIYO_NRS4018T1R0NDGJ_2P
PL600 = TOKO_FDVE0630-H-R47M-P3_2P
PL701 PL704 = TOKO_FDUE0640J-H_4P
PL900 PL902 PL903 = L_1812-1806
PL901 = MURAT_BLM18BD102SN1D_L0603_2P
PL1207 PL1211 = TOKO_FDSD0630-H-3R3M-P3_2P
PL1210 PL1212 = TOKO_FDSD0630-H-1R0M-P3_2P
PQ7 PQ904 PQ908 PQ1227 Q4 Q5 Q32 Q34 Q37 Q38 Q42 Q71 Q311 Q321 Q326 Q328 Q330 Q333 Q334 Q336 QC1 QC5 = SSM3K7002FU_SC70-3
PQ101 PQ102 = FDMS6673BZ_POWER56-8-5
PQ103 = AO4407AL_SO8
PQ204 PQ1228 Q35 Q305 Q316-Q320 Q327 QC4 QH3 QH4 = DMN66D0LDW-7_SOT363-6
PQ900 = FDV301N_NL_SOT23-3
PQ901 = RHU002N06_SOT323-3
PQ1207 PQ1209 PQ1215 = AON7406L_DFN8-5
PQ1208 PQ1210 = AON7212L_DFN8-5
PQ1211 PQ1223 = SIR472DP-T1-GE3_POWERPAK8-5
PQ1217 PQ1218 = AON6920_DFN5X6A-8-10
PQ1219 PQ1221 = SIR818DP-T1_POWERPAK-SO8-5
PQ1226 = FDMC7672S_MLP8-5
PR13 PR25 = R_1206_4P-D
PR23 PR30 PR35 PR46 PR219 PR306 PR402 PR405 PR503 PR508 PR509 PR512 PR513 PR516-PR518 PR521 PR604 PR610 PR611 PR720 PR721 PR723 PR736 PR911 PR918 PR936 PR954-PR956 R228 R249 R250 R253 R265 R538 R728 R819 R921 R925 R926 R931 R933 R934 R982-R984 R1012-R1017 R1031 R1090 R1091 R1107 RC11 RC49 RC53 RC56 RC92 RC96 RC98 RC99 RC107 RC145 RH130-RH133 RH137 RH273 RH293 RH297 RH309 RH310 RH313 RH336 RV8 = R0402_0OHM-NEW
PR24 R541 RH216 = R_0805NEW
PR26 PR208 PR209 PR302 PR400 PR406 PR504 PR606 PR711 PR743 PR942 RV1 = R_1206NEW
PR32 PR206 PR207 PR300 PR303 PR501 PR605 PR710 PR714 PR724 PR742 PR747 PR939 PR940 R531 R811 R1084 RH201 RH208 RH213 RH214 RH234 = R_0603NEW
PR119 PR120 PR722 R216 RH207 RH210 RH211 RH219 RH233 RH244 RH280 RH292 RH312 = R0603_0OHM-NEW
PT1-PT20 T1 T76 T81 T82 T123 T127 T166 T204 T208-T216 T218 T219 T223-T250 T252 T253 = TPC12
PU2 = ISL9519HRTZ-T_TQFN28_4X4
PU300 = RT8207MZQW_WQFN20_3X3
PU400 PU401 = SY8033BDBC_DFN10_3X3
PU500 = TPS51212DSCR_SON10_3X3
PU501 = RT8243BZQW_WQFN20_3X3
PU600 = TPS51461RGER_QFN24_4X4
PU700 = ISL95835HRTZ-T_TQFN40_5X5
PU702 = INA199A2DCKR_SC70-6
Q41 Q329 QH7 QH8 = AO3419L_SOT23-3
Q47 Q335 = SI2301CDS-T1-GE3_SOT23-3
Q70 = SI3457BDV-T1-E3_TSOP6
QC2 QV1 = BSS138-G_SOT23-3
QC3 = AO4728L_SO8
QC6 = AP2302GN-HF_SOT23-3
QD1 QD2 QH1 = BSS138_NL_SOT23-3
R222 R262 R556 R560 R565 R888-R893 R1004 R1005 = R_0402NEW: signal model: R_0402_R_0402
R555 = R_0402NEW: signal model: R_0402_0_0402_5__D
R741 R742 R1006-R1011 RH255 = R0402_0OHM-NEW: signal model: R_0402_R_0402
RC109 RH230 RH247 = R0805_0OHM-NEW
SW1 = SW_EVQP3S01K_4P
SW2 = SW_SKQGABE010_4P
U34 = KB9012BF-A3_LFBGA_128P
U48 = W25Q64CVSSIG_SO8
U635 = SN74LVC1G06DCKR_SC70-5
U636 = STM32F103RDY6TR_WLCSP_64P
U637 = DE303DLHCTR_LGA14_3X5
U638 = TX3GD20TR_LGA16_4X4
U652 = AT97SC3204-X2A14-AB_TSSOP28
U654 U655 = TPS22966DPUR_SON14_2X3
U656 U657 = G547I2P81U_MSOP8
UC1 = 74AHC1G09GW_TSSOP5
UC2 = SN74LVC1G07DCKR_SC70-5
UCPU1 = IVY-BRIDGE_BGA_1023P
UD1-UD16 = MT41K256M8DA-15E-M_FBGA_78P
UD17 UD18 = AT24C02B-TH-T_TSSOP8
UH1 = BD82QS77-QPRF-C1_BGA_1017P
UH5 = SN74AHC1G08DCKR_SC70-5
UI1 = SLG55584AVTR_TDFN8_2X2
URF1 = SKY13351-378LF_QFN6_1X1
UV1 = SN74CBT3257CPWR_TSSOP16
Y1 YH1 = Y_CM31532768DZFT_2P
Y2 = Y_X1H008000DI1H-W_4P
YH2 = Y_X3G025000DI1H-H_4P

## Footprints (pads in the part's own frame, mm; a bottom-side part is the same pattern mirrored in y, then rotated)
74AHC1G09GW_TSSOP5
  oval 0.381x1.346 smd: 1(0,0) 2(0.65,0) 3(1.3,0) 4(1.3,1.79) 5(0,1.79)
ACES_50271-00201-001_2P
  oval 0.787x1.6 smd: 1(0,0) 2(1.25,0)
  rect 2.108x2.997 smd: 3(-2.55,-2.9) 4(3.8,-2.9)
ACES_50281-0040N-001_4P
  oval 0.787x2.007 smd: 1(0,0) 2(-1.25,0) 3(-2.5,0) 4(-3.75,0)
  rect 2.007x2.489 smd: 5(2.2,-4.05) 6(-5.95,-4.05)
ACES_50281-00501-001_5P-T
  oval 0.787x2.007 smd: 1(0,0) 2(1.25,0) 3(2.5,0) 4(3.75,0) 5(5,0)
  rect 2.007x2.489 smd: 6(7.2,-4.05) 7(-2.2,-4.05)
ACES_50406-02071-001_20P
  oval 0.254x1.295 smd: 1(0,0) 2(0.5,0) 3(1,0) 4(1.5,0) 5(2,0) 6(2.5,0) 7(3,0) 8(3.5,0) 9(4,0) 10(4.5,0) 11(5,0) 12(5.5,0) 13(6,0) 14(6.5,0) 15(7,0) 16(7.5,0) 17(8,0) 18(8.5,0) 19(9,0) 20(9.5,0)
  rect 1.194x2.692 smd: 21(-2.4,1.95) 22(11.9,1.95)
  rect 2.311x1.295 smd: 23(0.85,3.9) 24(8.65,3.9)
ACES_50519-00401-P01_4P-T
  oval 0.508x1.448 smd: 1(0,0) 2(0.8,0) 3(1.6,0) 4(2.4,0)
  rect 1.803x1.905 smd: 5(-2.3,-3.125) 6(4.7,-3.125)
ACES_50699-03041-001_30P-T
  oval 0.229x0.787 smd: 1(0,0) 2(0.8,0) 3(1.6,0) 4(2.4,0) 5(3.2,0) 6(4,0) 7(4.8,0) 8(5.6,0) 9(6.4,0) 10(7.2,0) 11(8,0) 12(8.8,0) 13(9.6,0) 14(10.4,0) 15(11.2,0) 16(12,0) 17(12.8,0) 18(13.6,0) 19(14.4,0) 20(15.2,0) 21(16,0) 22(16.8,0) 23(17.6,0) 24(18.4,0) 25(19.2,0) 26(20,0) 27(20.8,0) 28(21.6,0) 29(22.4,0) 30(23.2,0)
  rect 0.559x1.295 smd: 31(-1.475,-3.3) 32(24.675,-3.3)
ACON_MAR2B-20K1200_20P-T
  round 0.94 hole 0.94 unplated: (-0.825,3.26) (6.825,3.26)
  oval 0.813x0.914 hole 0.61: 1(0,0) 3(0.5,1) 5(1.5,1) 7(2,0) 9(2.5,-1) 11(3.5,-1) 13(4,0) 15(4.5,1) 17(5.5,1) 19(6,0)
  oval 0.356x2.007 smd: 2(0.3,2.91) 4(0.9,2.91) 6(1.5,2.91) 8(2.1,2.91) 10(2.7,2.91) 12(3.3,2.91) 14(3.9,2.91) 16(4.5,2.91) 18(5.1,2.91) 20(5.7,2.91)
  oval 1.092x2.007 hole 0.711x1.6: 21(-2.1,1.66) 23(8.1,1.66)
  oval 1.092x1.803 hole 0.711x1.397: 22(-2.8,-3.04) 24(8.8,-3.04)
ACON_TARAG-9V1391_9P-T
  round 1.295 hole 0.711: 1(0,0) 2(-2.5,0) 3(-4.5,0) 4(-7,0) 5(-7.5,-1.5) 6(-5.5,-1.5) 7(-3.5,-1.5) 8(-1.5,-1.5) 9(0.5,-1.5)
  oval 1.499x2.489 hole 0.889x1.905: 10(-9.9,-0.75) 13(2.9,-0.75)
  oval 1.499x2.21 hole 0.889x1.6: 11(-11.35,-9.2) 12(4.35,-9.2)
AO3419L_SOT23-3
  oval 1.016x1.524 smd: 1(0,0) 2(0.965,2.083) 3(-0.965,2.083)
AO4407AL_SO8
  oval 0.635x1.854 smd: 1(0,0) 2(1.27,0) 3(2.54,0) 4(3.81,0) 5(3.81,5.165) 6(2.54,5.165) 7(1.27,5.165) 8(0,5.165)
AO4728L_SO8
  oval 0.635x1.854 smd: 1(0,0) 2(1.27,0) 3(2.54,0) 4(3.81,0) 5(3.81,5.165) 6(2.54,5.165) 7(1.27,5.165) 8(0,5.165)
AON6920_DFN5X6A-8-10
  oval 0.508x0.66 smd: 1(0,0) 2(1.27,0) 3(2.54,0) 4(3.81,0) 5(3.81,5.5) 6(2.54,5.5) 7(1.27,5.5) 8(0,5.5)
  rect 4.039x2.565 smd: 9(1.9,3.49)
  rect 4.039x0.991 smd: 10(1.9,1.105)
AON7212L_DFN8-5
  oval 0.406x0.991 smd: 1(0,0) 2(0.66,0) 3(1.32,0) 4(1.98,0)
  custom 0.559x0.559 smd: 5(0.99,2.247)
AON7406L_DFN8-5
  oval 0.406x0.991 smd: 1(0,0) 2(0.66,0) 3(1.32,0) 4(1.98,0)
  custom 0.559x0.559 smd: 5(0.99,2.247)
AP2302GN-HF_SOT23-3
  oval 1.016x1.524 smd: 1(0,0) 2(0.965,2.083) 3(-0.965,2.083)
AT24C02B-TH-T_TSSOP8
  oval 0.381x1.626 smd: 1(0,0) 2(0.65,0) 3(1.3,0) 4(1.95,0) 5(1.95,5.8) 6(1.3,5.8) 7(0.65,5.8) 8(0,5.8)
AT97SC3204-X2A14-AB_TSSOP28
  oval 0.381x1.626 smd: 1(0,0) 2(0.65,0) 3(1.3,0) 4(1.95,0) 5(2.6,0) 6(3.25,0) 7(3.9,0) 8(4.55,0) 9(5.2,0) 10(5.85,0) 11(6.5,0) 12(7.15,0) 13(7.8,0) 14(8.45,0) 15(8.45,5.8) 16(7.8,5.8) 17(7.15,5.8) 18(6.5,5.8) 19(5.85,5.8) 20(5.2,5.8) 21(4.55,5.8) 22(3.9,5.8) 23(3.25,5.8) 24(2.6,5.8) 25(1.95,5.8) 26(1.3,5.8) 27(0.65,5.8) 28(0,5.8)
BAS40CW_SOT323-3
  oval 0.813x0.914 smd: 1(0,0) 2(0.65,1.6) 3(-0.65,1.6)
BAT54CW-7-F_SOT323-3
  oval 0.711x0.889 smd: 1(0,0) 2(-0.65,-1.9) 3(0.65,-1.9)
BAV99W-7-F_SOT323-3
  oval 0.813x0.914 smd: 1(0,0) 2(0.65,1.6) 3(-0.65,1.6)
BD82QS77-QPRF-C1_BGA_1017P
  round 0.356 smd: A4(-1.046,0) A5(-1.64,0) A48(-19.442,0) A49(-20.035,0) A51(-20.628,0) BH1(0,19.442) BH51(-20.628,19.442) BJ1(0,20.035) BJ3(-0.593,20.035) BJ49(-20.035,20.035) BJ51(-20.628,20.035) BL1(0,20.628) BL3(-0.593,20.628) BL4(-1.186,20.628) BL48(-19.442,20.628) BL49(-20.035,20.628) BL51(-20.628,20.628) C3(-0.555,0.555) C49(-20.035,0.593) C51(-20.628,0.593) D1(0,1.046) D51(-20.628,1.186) E1(0,1.64)
  round 0.305 smd: A7(-2.592,0) A9(-3.405,0) A11(-4.218,0) A13(-5.031,0) A15(-5.844,0) A17(-6.656,0) A19(-7.469,0) A21(-8.282,0) A23(-9.095,0) A25(-9.908,0) A27(-10.72,0) A29(-11.533,0) A31(-12.346,0) A33(-13.159,0) A35(-13.972,0) A37(-14.784,0) A39(-15.597,0) A41(-16.41,0) A43(-17.223,0) A45(-18.036,0) A47(-18.848,0) AA1(0,8.282) AA3(-0.864,8.282) AA7(-2.324,7.901) AA9(-3.188,7.901) AA11(-4.051,7.901) AA13(-4.915,7.901) AA39(-15.713,7.901) AA41(-16.577,7.901) AA43(-17.44,7.901) AA45(-18.304,7.901) AA49(-19.764,8.282) AA51(-20.628,8.282) AB2(-0.432,8.688) AB4(-1.295,8.688) AB6(-1.892,8.384) AB8(-2.756,8.384) AB10(-3.619,8.384) AB12(-4.483,8.384) AB15(-5.691,8.333) AB17(-6.529,8.333) AB19(-7.368,8.333) AB21(-8.206,8.333) AB23(-9.044,8.333) AB25(-9.882,8.333) AB27(-10.72,8.333) AB29(-11.559,8.333) AB31(-12.397,8.333) AB33(-13.235,8.333) AB35(-14.073,8.333) AB37(-14.911,8.333) AB40(-16.145,8.384) AB42(-17.008,8.384) AB44(-17.872,8.384) AB46(-18.736,8.384) AB48(-19.332,8.688) AB50(-20.196,8.688) AC1(0,9.095) AC3(-0.864,9.095) AC7(-2.324,8.866) AC9(-3.188,8.866) AC11(-4.051,8.866) AC13(-4.915,8.866) AC15(-5.691,8.993) AC17(-6.529,8.993) AC19(-7.368,8.993) AC21(-8.206,8.993) AC23(-9.044,8.993) AC25(-9.882,8.993) AC27(-10.72,8.993) AC29(-11.559,8.993) AC31(-12.397,8.993) AC33(-13.235,8.993) AC35(-14.073,8.993) AC37(-14.911,8.993) AC39(-15.713,8.866) AC41(-16.577,8.866) AC43(-17.44,8.866) AC45(-18.304,8.866) AC49(-19.764,9.095) AC51(-20.628,9.095) AD2(-0.432,9.501) AD4(-1.295,9.501) AD6(-1.892,9.349) AD8(-2.756,9.349) AD10(-3.619,9.349) AD12(-4.483,9.349) AD40(-16.145,9.349) AD42(-17.008,9.349) AD44(-17.872,9.349) AD46(-18.736,9.349) AD48(-19.332,9.501) AD50(-20.196,9.501) AE1(0,9.908) AE3(-0.864,9.908) AE7(-2.324,9.831) AE9(-3.188,9.831) AE11(-4.051,9.831) AE13(-4.915,9.831) AE15(-5.691,9.654) AE17(-6.529,9.654) AE19(-7.368,9.654) AE21(-8.206,9.654) AE23(-9.044,9.654) AE25(-9.882,9.654) AE27(-10.72,9.654) AE29(-11.559,9.654) AE31(-12.397,9.654) AE33(-13.235,9.654) AE35(-14.073,9.654) AE37(-14.911,9.654) AE39(-15.713,9.831) AE41(-16.577,9.831) AE43(-17.44,9.831) AE45(-18.304,9.831) AE49(-19.764,9.908) AE51(-20.628,9.908) AF2(-0.432,10.314) AF4(-1.295,10.314) AF6(-1.892,10.314) AF8(-2.756,10.314) AF10(-3.619,10.314) AF12(-4.483,10.314) AF15(-5.691,10.314) AF17(-6.529,10.314) AF19(-7.368,10.314) AF21(-8.206,10.314) AF23(-9.044,10.314) AF25(-9.882,10.314) AF27(-10.72,10.314) AF29(-11.559,10.314) AF31(-12.397,10.314) AF33(-13.235,10.314) AF35(-14.073,10.314) AF37(-14.911,10.314) AF40(-16.145,10.314) AF42(-17.008,10.314) AF44(-17.872,10.314) AF46(-18.736,10.314) AF48(-19.332,10.314) AF50(-20.196,10.314) AG1(0,10.72) AG3(-0.864,10.72) AG7(-2.324,10.797) AG9(-3.188,10.797) AG11(-4.051,10.797) AG13(-4.915,10.797) AG15(-5.691,10.974) AG17(-6.529,10.974) AG19(-7.368,10.974) AG21(-8.206,10.974) AG23(-9.044,10.974) AG25(-9.882,10.974) AG27(-10.72,10.974) AG29(-11.559,10.974) AG31(-12.397,10.974) AG33(-13.235,10.974) AG35(-14.073,10.974) AG37(-14.911,10.974) AG39(-15.713,10.797) AG41(-16.577,10.797) AG43(-17.44,10.797) AG45(-18.304,10.797) AG49(-19.764,10.72) AG51(-20.628,10.72) AH2(-0.432,11.127) AH4(-1.295,11.127) AH6(-1.892,11.279) AH8(-2.756,11.279) AH10(-3.619,11.279) AH12(-4.483,11.279) AH40(-16.145,11.279) AH42(-17.008,11.279) AH44(-17.872,11.279) AH46(-18.736,11.279) AH48(-19.332,11.127) AH50(-20.196,11.127) AJ1(0,11.533) AJ3(-0.864,11.533) AJ7(-2.324,11.762) AJ9(-3.188,11.762) AJ11(-4.051,11.762) AJ13(-4.915,11.762) AJ15(-5.691,11.635) AJ17(-6.529,11.635) AJ19(-7.368,11.635) AJ21(-8.206,11.635) AJ23(-9.044,11.635) AJ25(-9.882,11.635) AJ27(-10.72,11.635) AJ29(-11.559,11.635) AJ31(-12.397,11.635) AJ33(-13.235,11.635) AJ35(-14.073,11.635) AJ37(-14.911,11.635) AJ39(-15.713,11.762) AJ41(-16.577,11.762) AJ43(-17.44,11.762) AJ45(-18.304,11.762) AJ49(-19.764,11.533) AJ51(-20.628,11.533) AK2(-0.432,11.94) AK4(-1.295,11.94) AK6(-1.892,12.244) AK8(-2.756,12.244) AK10(-3.619,12.244) AK12(-4.483,12.244) AK15(-5.691,12.295) AK17(-6.529,12.295) AK19(-7.368,12.295) AK21(-8.206,12.295) AK23(-9.044,12.295) AK25(-9.882,12.295) AK27(-10.72,12.295) AK29(-11.559,12.295) AK31(-12.397,12.295) AK33(-13.235,12.295) AK35(-14.073,12.295) AK37(-14.911,12.295) AK40(-16.145,12.244) AK42(-17.008,12.244) AK44(-17.872,12.244) AK46(-18.736,12.244) AK48(-19.332,11.94) AK50(-20.196,11.94) AL1(0,12.346) AL3(-0.864,12.346) AL7(-2.324,12.727) AL9(-3.188,12.727) AL11(-4.051,12.727) AL13(-4.915,12.727) AL39(-15.713,12.727) AL41(-16.577,12.727) AL43(-17.44,12.727) AL45(-18.304,12.727) AL49(-19.764,12.346) AL51(-20.628,12.346) AM2(-0.432,12.752) AM4(-1.295,12.752) AM15(-5.691,12.956) AM17(-6.529,12.956) AM19(-7.368,12.956) AM21(-8.206,12.956) AM23(-9.044,12.956) AM25(-9.882,12.956) AM27(-10.72,12.956) AM29(-11.559,12.956) AM31(-12.397,12.956) AM33(-13.235,12.956) AM35(-14.073,12.956) AM37(-14.911,12.956) AM48(-19.332,12.752) AM50(-20.196,12.752) AN1(0,13.159) AN3(-0.864,13.159) AN6(-1.892,13.21) AN8(-2.756,13.21) AN10(-3.619,13.21) AN12(-4.483,13.21) AN40(-16.145,13.21) AN42(-17.008,13.21) AN44(-17.872,13.21) AN46(-18.736,13.21) AN49(-19.764,13.159) AN51(-20.628,13.159) AP2(-0.432,13.565) AP4(-1.295,13.565) AP7(-2.324,13.692) AP9(-3.188,13.692) AP11(-4.051,13.692) AP13(-4.915,13.692) AP15(-5.691,13.616) AP17(-6.529,13.616) AP19(-7.368,13.616) AP21(-8.206,13.616) AP23(-9.044,13.616) AP25(-9.882,13.616) AP27(-10.72,13.616) AP29(-11.559,13.616) AP31(-12.397,13.616) AP33(-13.235,13.616) AP35(-14.073,13.616) AP37(-14.911,13.616) AP39(-15.713,13.692) AP41(-16.577,13.692) AP43(-17.44,13.692) AP45(-18.304,13.692) AP48(-19.332,13.565) AP50(-20.196,13.565) AR1(0,13.972) AR3(-0.864,13.972) AR6(-1.892,14.175) AR8(-2.756,14.175) AR10(-3.619,14.175) AR12(-4.483,14.175) AR15(-5.691,14.276) AR17(-6.529,14.276) AR19(-7.368,14.276) AR21(-8.206,14.276) AR23(-9.044,14.276) AR25(-9.882,14.276) AR27(-10.72,14.276) AR29(-11.559,14.276) AR31(-12.397,14.276) AR33(-13.235,14.276) AR35(-14.073,14.276) AR37(-14.911,14.276) AR40(-16.145,14.175) AR42(-17.008,14.175) AR44(-17.872,14.175) AR46(-18.736,14.175) AR49(-19.764,13.972) AR51(-20.628,13.972) AT2(-0.432,14.378) AT4(-1.295,14.378) AT7(-2.324,14.657) AT9(-3.188,14.657) AT11(-4.051,14.657) AT13(-4.915,14.657) AT39(-15.713,14.657) AT41(-16.577,14.657) AT43(-17.44,14.657) AT45(-18.304,14.657) AT48(-19.332,14.378) AT50(-20.196,14.378) AU1(0,14.784) AU3(-0.864,14.784) AU6(-1.892,15.14) AU8(-2.756,15.14) AU10(-3.619,15.14) AU12(-4.483,15.14) AU15(-5.691,14.937) AU17(-6.529,14.937) AU19(-7.368,14.937) AU21(-8.206,14.937) AU23(-9.044,14.937) AU25(-9.882,14.937) AU27(-10.72,14.937) AU29(-11.559,14.937) AU31(-12.397,14.937) AU33(-13.235,14.937) AU35(-14.073,14.937) AU37(-14.911,14.937) AU40(-16.145,15.14) AU42(-17.008,15.14) AU44(-17.872,15.14) AU46(-18.736,15.14) AU49(-19.764,14.784) AU51(-20.628,14.784) AV2(-0.432,15.191) AV4(-1.295,15.191) AV48(-19.332,15.191) AV50(-20.196,15.191) AW1(0,15.597) AW3(-0.864,15.597) AW7(-2.324,15.623) AW9(-3.188,15.623) AW11(-4.051,15.623) AW13(-4.915,15.623) AW16(-5.971,15.713) AW18(-6.936,15.713) AW21(-7.901,15.713) AW23(-8.866,15.713) AW25(-9.831,15.713) AW27(-10.797,15.713) AW29(-11.762,15.713) AW31(-12.727,15.713) AW34(-13.692,15.713) AW36(-14.657,15.713) AW39(-15.623,15.713) AW41(-16.577,15.623) AW43(-17.44,15.623) AW45(-18.304,15.623) AW49(-19.764,15.597) AW51(-20.628,15.597) AY2(-0.432,16.004) AY4(-1.295,16.004) AY6(-1.892,16.105) AY8(-2.756,16.105) AY10(-3.619,16.105) AY12(-4.483,16.105) AY15(-5.488,16.145) AY17(-6.453,16.145) AY19(-7.418,16.145) AY22(-8.384,16.145) AY24(-9.349,16.145) AY26(-10.314,16.145) AY28(-11.279,16.145) AY30(-12.244,16.145) AY33(-13.21,16.145) AY35(-14.175,16.145) AY37(-15.14,16.145) AY40(-16.105,16.145) AY42(-17.008,16.105) AY44(-17.872,16.105) AY46(-18.736,16.105) AY48(-19.332,16.004) AY50(-20.196,16.004) B6(-2.186,0.432) B8(-2.999,0.432) B10(-3.812,0.432) B12(-4.624,0.432) B14(-5.437,0.432) B16(-6.25,0.432) B18(-7.063,0.432) B20(-7.876,0.432) B22(-8.688,0.432) B24(-9.501,0.432) B26(-10.314,0.432) B28(-11.127,0.432) B30(-11.94,0.432) B32(-12.752,0.432) B34(-13.565,0.432) B36(-14.378,0.432) B38(-15.191,0.432) B40(-16.004,0.432) B42(-16.816,0.432) B44(-17.629,0.432) B46(-18.442,0.432) BA1(0,16.41) BA3(-0.864,16.41) BA7(-2.324,16.588) BA9(-3.188,16.588) BA11(-4.051,16.588) BA13(-5.005,16.577) BA16(-5.971,16.577) BA18(-6.936,16.577) BA21(-7.901,16.577) BA23(-8.866,16.577) BA25(-9.831,16.577) BA27(-10.797,16.577) BA29(-11.762,16.577) BA31(-12.727,16.577) BA34(-13.692,16.577) BA36(-14.657,16.577) BA39(-15.623,16.577) BA41(-16.588,16.577) BA43(-17.44,16.588) BA45(-18.304,16.588) BA49(-19.764,16.41) BA51(-20.628,16.41) BB2(-0.432,16.816) BB4(-1.295,16.816) BB6(-1.892,17.07) BB8(-2.756,17.07) BB10(-3.558,17.07) BB12(-4.523,17.008) BB15(-5.488,17.008) BB17(-6.453,17.008) BB19(-7.418,17.008) BB22(-8.384,17.008) BB24(-9.349,17.008) BB26(-10.314,17.008) BB28(-11.279,17.008) BB30(-12.244,17.008) BB33(-13.21,17.008) BB35(-14.175,17.008) BB37(-15.14,17.008) BB40(-16.105,17.008) BB42(-17.07,17.07) BB44(-17.872,17.07) BB46(-18.736,17.07) BB48(-19.332,16.816) BB50(-20.196,16.816) BC1(0,17.223) BC3(-0.864,17.223) BC7(-2.324,17.553) BC9(-3.024,17.604) BC11(-4.04,17.44) BC13(-5.005,17.44) BC16(-5.971,17.44) BC18(-6.936,17.44) BC21(-7.901,17.44) BC23(-8.866,17.44) BC25(-9.831,17.44) BC27(-10.797,17.44) BC29(-11.762,17.44) BC31(-12.727,17.44) BC34(-13.692,17.44) BC36(-14.657,17.44) BC39(-15.623,17.44) BC41(-16.588,17.44) BC43(-17.604,17.604) BC45(-18.304,17.553) BC49(-19.764,17.223) BC51(-20.628,17.223) BD2(-0.432,17.629) BD4(-1.295,17.629) BD10(-3.558,17.872) BD12(-4.523,17.872) BD15(-5.488,17.872) BD17(-6.453,17.872) BD19(-7.418,17.872) BD22(-8.384,17.872) BD24(-9.349,17.872) BD26(-10.314,17.872) BD28(-11.279,17.872) BD30(-12.244,17.872) BD33(-13.21,17.872) BD35(-14.175,17.872) BD37(-15.14,17.872) BD40(-16.105,17.872) BD42(-17.07,17.872) BD48(-19.332,17.629) BD50(-20.196,17.629) BE1(0,18.036) BE3(-0.864,18.036) BE6(-1.892,18.036) BE7(-2.491,18.137) BE9(-3.075,18.304) BE11(-4.04,18.304) BE13(-5.005,18.304) BE16(-5.971,18.304) BE18(-6.936,18.304) BE21(-7.901,18.304) BE23(-8.866,18.304) BE25(-9.831,18.304) BE27(-10.797,18.304) BE29(-11.762,18.304) BE31(-12.727,18.304) BE34(-13.692,18.304) BE36(-14.657,18.304) BE39(-15.623,18.304) BE41(-16.588,18.304) BE43(-17.553,18.304) BE45(-18.137,18.137) BE46(-18.736,18.036) BE49(-19.764,18.036) BE51(-20.628,18.036) BF2(-0.432,18.442) BF4(-1.295,18.442) BF6(-1.881,18.747) BF7(-2.592,18.736) BF10(-3.558,18.736) BF12(-4.523,18.736) BF15(-5.488,18.736) BF17(-6.453,18.736) BF19(-7.418,18.736) BF22(-8.384,18.736) BF24(-9.349,18.736) BF26(-10.314,18.736) BF28(-11.279,18.736) BF30(-12.244,18.736) BF33(-13.21,18.736) BF35(-14.175,18.736) BF37(-15.14,18.736) BF40(-16.105,18.736) BF42(-17.07,18.736) BF45(-18.036,18.736) BF46(-18.747,18.747) BF48(-19.332,18.442) BF50(-20.196,18.442) BG1(0,18.848) BG3(-0.864,18.848) BG49(-19.764,18.848) BG51(-20.628,18.848) BH3(-0.61,19.442) BH4(-1.297,19.331) BH6(-2.186,19.329) BH8(-2.999,19.329) BH10(-3.812,19.332) BH12(-4.624,19.332) BH14(-5.437,19.332) BH16(-6.25,19.332) BH18(-7.063,19.332) BH20(-7.876,19.332) BH22(-8.688,19.332) BH24(-9.501,19.332) BH26(-10.314,19.332) BH28(-11.127,19.332) BH30(-11.94,19.332) BH32(-12.752,19.332) BH34(-13.565,19.332) BH36(-14.378,19.332) BH38(-15.191,19.332) BH40(-16.004,19.332) BH42(-16.816,19.332) BH44(-17.629,19.332) BH46(-18.442,19.332) BH48(-19.331,19.331) BH49(-20.018,19.442) BJ4(-1.186,20.018) BJ5(-1.78,19.764) BJ7(-2.592,19.764) BJ9(-3.405,19.764) BJ11(-4.218,19.764) BJ13(-5.031,19.764) BJ15(-5.844,19.764) BJ17(-6.656,19.764) BJ19(-7.469,19.764) BJ21(-8.282,19.764) BJ23(-9.095,19.764) BJ25(-9.908,19.764) BJ27(-10.72,19.764) BJ29(-11.533,19.764) BJ31(-12.346,19.764) BJ33(-13.159,19.764) BJ35(-13.972,19.764) BJ37(-14.784,19.764) BJ39(-15.597,19.764) BJ41(-16.41,19.764) BJ43(-17.223,19.764) BJ45(-18.036,19.764) BJ47(-18.848,19.764) BJ48(-19.442,20.018) BK6(-2.186,20.196) BK8(-2.999,20.196) BK10(-3.812,20.196) BK12(-4.624,20.196) BK14(-5.437,20.196) BK16(-6.25,20.196) BK18(-7.063,20.196) BK20(-7.876,20.196) BK22(-8.688,20.196) BK24(-9.501,20.196) BK26(-10.314,20.196) BK28(-11.127,20.196) BK30(-11.94,20.196) BK32(-12.752,20.196) BK34(-13.565,20.196) BK36(-14.378,20.196) BK38(-15.191,20.196) BK40(-16.004,20.196) BK42(-16.816,20.196) BK44(-17.629,20.196) BK46(-18.442,20.196) BL5(-1.78,20.628) BL7(-2.592,20.628) BL9(-3.405,20.628) BL11(-4.218,20.628) BL13(-5.031,20.628) BL15(-5.844,20.628) BL17(-6.656,20.628) BL19(-7.469,20.628) BL21(-8.282,20.628) BL23(-9.095,20.628) BL25(-9.908,20.628) BL27(-10.72,20.628) BL29(-11.533,20.628) BL31(-12.346,20.628) BL33(-13.159,20.628) BL35(-13.972,20.628) BL37(-14.784,20.628) BL39(-15.597,20.628) BL41(-16.41,20.628) BL43(-17.223,20.628) BL45(-18.036,20.628) BL47(-18.848,20.628) C4(-1.186,0.61) C5(-1.78,0.864) C7(-2.592,0.864) C9(-3.405,0.864) C11(-4.218,0.864) C13(-5.031,0.864) C15(-5.844,0.864) C17(-6.656,0.864) C19(-7.469,0.864) C21(-8.282,0.864) C23(-9.095,0.864) C25(-9.908,0.864) C27(-10.72,0.864) C29(-11.533,0.864) C31(-12.346,0.864) C33(-13.159,0.864) C35(-13.972,0.864) C37(-14.784,0.864) C39(-15.597,0.864) C41(-16.41,0.864) C43(-17.223,0.864) C45(-18.036,0.864) C47(-18.848,0.864) C48(-19.442,0.61) D3(-0.61,1.186) D4(-1.297,1.297) D6(-2.186,1.295) D8(-2.999,1.295) D10(-3.812,1.295) D12(-4.624,1.295) D14(-5.437,1.295) D16(-6.25,1.295) D18(-7.063,1.295) D20(-7.876,1.295) D22(-8.688,1.295) D24(-9.501,1.295) D26(-10.314,1.295) D28(-11.127,1.295) D30(-11.94,1.295) D32(-12.752,1.295) D34(-13.565,1.295) D36(-14.378,1.295) D38(-15.191,1.295) D40(-16.004,1.295) D42(-16.816,1.295) D44(-17.629,1.295) D46(-18.442,1.295) D48(-19.331,1.297) D49(-20.018,1.186) E3(-0.864,1.78) E49(-19.764,1.78) E51(-20.628,1.78) F2(-0.432,2.186) F4(-1.295,2.186) F6(-1.881,1.881) F7(-2.592,1.892) F10(-3.558,1.892) F12(-4.523,1.892) F15(-5.488,1.892) F17(-6.453,1.892) F19(-7.418,1.892) F22(-8.384,1.892) F24(-9.349,1.892) F26(-10.314,1.892) F28(-11.279,1.892) F30(-12.244,1.892) F33(-13.21,1.892) F35(-14.175,1.892) F37(-15.14,1.892) F40(-16.105,1.892) F42(-17.07,1.892) F45(-18.036,1.892) F46(-18.747,1.881) F48(-19.332,2.186) F50(-20.196,2.186) G1(0,2.592) G3(-0.864,2.592) G6(-1.892,2.592) G7(-2.491,2.491) G9(-3.075,2.324) G11(-4.04,2.324) G13(-5.005,2.324) G16(-5.971,2.324) G18(-6.936,2.324) G21(-7.901,2.324) G23(-8.866,2.324) G25(-9.831,2.324) G27(-10.797,2.324) G29(-11.762,2.324) G31(-12.727,2.324) G34(-13.692,2.324) G36(-14.657,2.324) G39(-15.623,2.324) G41(-16.588,2.324) G43(-17.553,2.324) G45(-18.137,2.491) G46(-18.736,2.592) G49(-19.764,2.592) G51(-20.628,2.592) H2(-0.432,2.999) H4(-1.295,2.999) H10(-3.558,2.756) H12(-4.523,2.756) H15(-5.488,2.756) H17(-6.453,2.756) H19(-7.418,2.756) H22(-8.384,2.756) H24(-9.349,2.756) H26(-10.314,2.756) H28(-11.279,2.756) H30(-12.244,2.756) H33(-13.21,2.756) H35(-14.175,2.756) H37(-15.14,2.756) H40(-16.105,2.756) H42(-17.07,2.756) H48(-19.332,2.999) H50(-20.196,2.999) J1(0,3.405) J3(-0.864,3.405) J7(-2.324,3.075) J9(-3.024,3.024) J11(-4.04,3.188) J13(-5.005,3.188) J16(-5.971,3.188) J18(-6.936,3.188) J21(-7.901,3.188) J23(-8.866,3.188) J25(-9.831,3.188) J27(-10.797,3.188) J29(-11.762,3.188) J31(-12.727,3.188) J34(-13.692,3.188) J36(-14.657,3.188) J39(-15.623,3.188) J41(-16.588,3.188) J43(-17.604,3.024) J45(-18.304,3.075) J49(-19.764,3.405) J51(-20.628,3.405) K2(-0.432,3.812) K4(-1.295,3.812) K6(-1.892,3.558) K8(-2.756,3.558) K10(-3.558,3.558) K12(-4.523,3.619) K15(-5.488,3.619) K17(-6.453,3.619) K19(-7.418,3.619) K22(-8.384,3.619) K24(-9.349,3.619) K26(-10.314,3.619) K28(-11.279,3.619) K30(-12.244,3.619) K33(-13.21,3.619) K35(-14.175,3.619) K37(-15.14,3.619) K40(-16.105,3.619) K42(-17.07,3.558) K44(-17.872,3.558) K46(-18.736,3.558) K48(-19.332,3.812) K50(-20.196,3.812) L1(0,4.218) L3(-0.864,4.218) L7(-2.324,4.04) L9(-3.188,4.04) L11(-4.04,4.051) L13(-5.005,4.051) L16(-5.971,4.051) L18(-6.936,4.051) L21(-7.901,4.051) L23(-8.866,4.051) L25(-9.831,4.051) L27(-10.797,4.051) L29(-11.762,4.051) L31(-12.727,4.051) L34(-13.692,4.051) L36(-14.657,4.051) L39(-15.623,4.051) L41(-16.577,4.04) L43(-17.44,4.04) L45(-18.304,4.04) L49(-19.764,4.218) L51(-20.628,4.218) M2(-0.432,4.624) M4(-1.295,4.624) M6(-1.892,4.523) M8(-2.756,4.523) M10(-3.619,4.523) M12(-4.523,4.483) M15(-5.488,4.483) M17(-6.453,4.483) M19(-7.418,4.483) M22(-8.384,4.483) M24(-9.349,4.483) M26(-10.314,4.483) M28(-11.279,4.483) M30(-12.244,4.483) M33(-13.21,4.483) M35(-14.175,4.483) M37(-15.14,4.483) M40(-16.145,4.523) M42(-17.008,4.523) M44(-17.872,4.523) M46(-18.736,4.523) M48(-19.332,4.624) M50(-20.196,4.624) N1(0,5.031) N3(-0.864,5.031) N7(-2.324,5.005) N9(-3.188,5.005) N11(-4.051,5.005) N13(-5.005,4.915) N16(-5.971,4.915) N18(-6.936,4.915) N21(-7.901,4.915) N23(-8.866,4.915) N25(-9.831,4.915) N27(-10.797,4.915) N29(-11.762,4.915) N31(-12.727,4.915) N34(-13.692,4.915) N36(-14.657,4.915) N39(-15.713,5.005) N41(-16.577,5.005) N43(-17.44,5.005) N45(-18.304,5.005) N49(-19.764,5.031) N51(-20.628,5.031) P2(-0.432,5.437) P4(-1.295,5.437) P48(-19.332,5.437) P50(-20.196,5.437) R1(0,5.844) R3(-0.864,5.844) R6(-1.892,5.488) R8(-2.756,5.488) R10(-3.619,5.488) R12(-4.483,5.488) R15(-5.691,5.691) R17(-6.529,5.691) R19(-7.368,5.691) R21(-8.206,5.691) R23(-9.044,5.691) R25(-9.882,5.691) R27(-10.72,5.691) R29(-11.559,5.691) R31(-12.397,5.691) R33(-13.235,5.691) R35(-14.073,5.691) R37(-14.911,5.691) R40(-16.145,5.488) R42(-17.008,5.488) R44(-17.872,5.488) R46(-18.736,5.488) R49(-19.764,5.844) R51(-20.628,5.844) T2(-0.432,6.25) T4(-1.295,6.25) T7(-2.324,5.971) T9(-3.188,5.971) T11(-4.051,5.971) T13(-4.915,5.971) T39(-15.713,5.971) T41(-16.577,5.971) T43(-17.44,5.971) T45(-18.304,5.971) T48(-19.332,6.25) T50(-20.196,6.25) U1(0,6.656) U3(-0.864,6.656) U6(-1.892,6.453) U8(-2.756,6.453) U10(-3.619,6.453) U12(-4.483,6.453) U15(-5.691,6.352) U17(-6.529,6.352) U19(-7.368,6.352) U21(-8.206,6.352) U23(-9.044,6.352) U25(-9.882,6.352) U27(-10.72,6.352) U29(-11.559,6.352) U31(-12.397,6.352) U33(-13.235,6.352) U35(-14.073,6.352) U37(-14.911,6.352) U40(-16.145,6.453) U42(-17.008,6.453) U44(-17.872,6.453) U46(-18.736,6.453) U49(-19.764,6.656) U51(-20.628,6.656) V2(-0.432,7.063) V4(-1.295,7.063) V7(-2.324,6.936) V9(-3.188,6.936) V11(-4.051,6.936) V13(-4.915,6.936) V15(-5.691,7.012) V17(-6.529,7.012) V19(-7.368,7.012) V21(-8.206,7.012) V23(-9.044,7.012) V25(-9.882,7.012) V27(-10.72,7.012) V29(-11.559,7.012) V31(-12.397,7.012) V33(-13.235,7.012) V35(-14.073,7.012) V37(-14.911,7.012) V39(-15.713,6.936) V41(-16.577,6.936) V43(-17.44,6.936) V45(-18.304,6.936) V48(-19.332,7.063) V50(-20.196,7.063) W1(0,7.469) W3(-0.864,7.469) W6(-1.892,7.418) W8(-2.756,7.418) W10(-3.619,7.418) W12(-4.483,7.418) W40(-16.145,7.418) W42(-17.008,7.418) W44(-17.872,7.418) W46(-18.736,7.418) W49(-19.764,7.469) W51(-20.628,7.469) Y2(-0.432,7.876) Y4(-1.295,7.876) Y15(-5.691,7.672) Y17(-6.529,7.672) Y19(-7.368,7.672) Y21(-8.206,7.672) Y23(-9.044,7.672) Y25(-9.882,7.672) Y27(-10.72,7.672) Y29(-11.559,7.672) Y31(-12.397,7.672) Y33(-13.235,7.672) Y35(-14.073,7.672) Y37(-14.911,7.672) Y48(-19.332,7.876) Y50(-20.196,7.876)
